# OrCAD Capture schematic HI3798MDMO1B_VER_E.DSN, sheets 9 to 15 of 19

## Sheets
9 SHEET09: size A
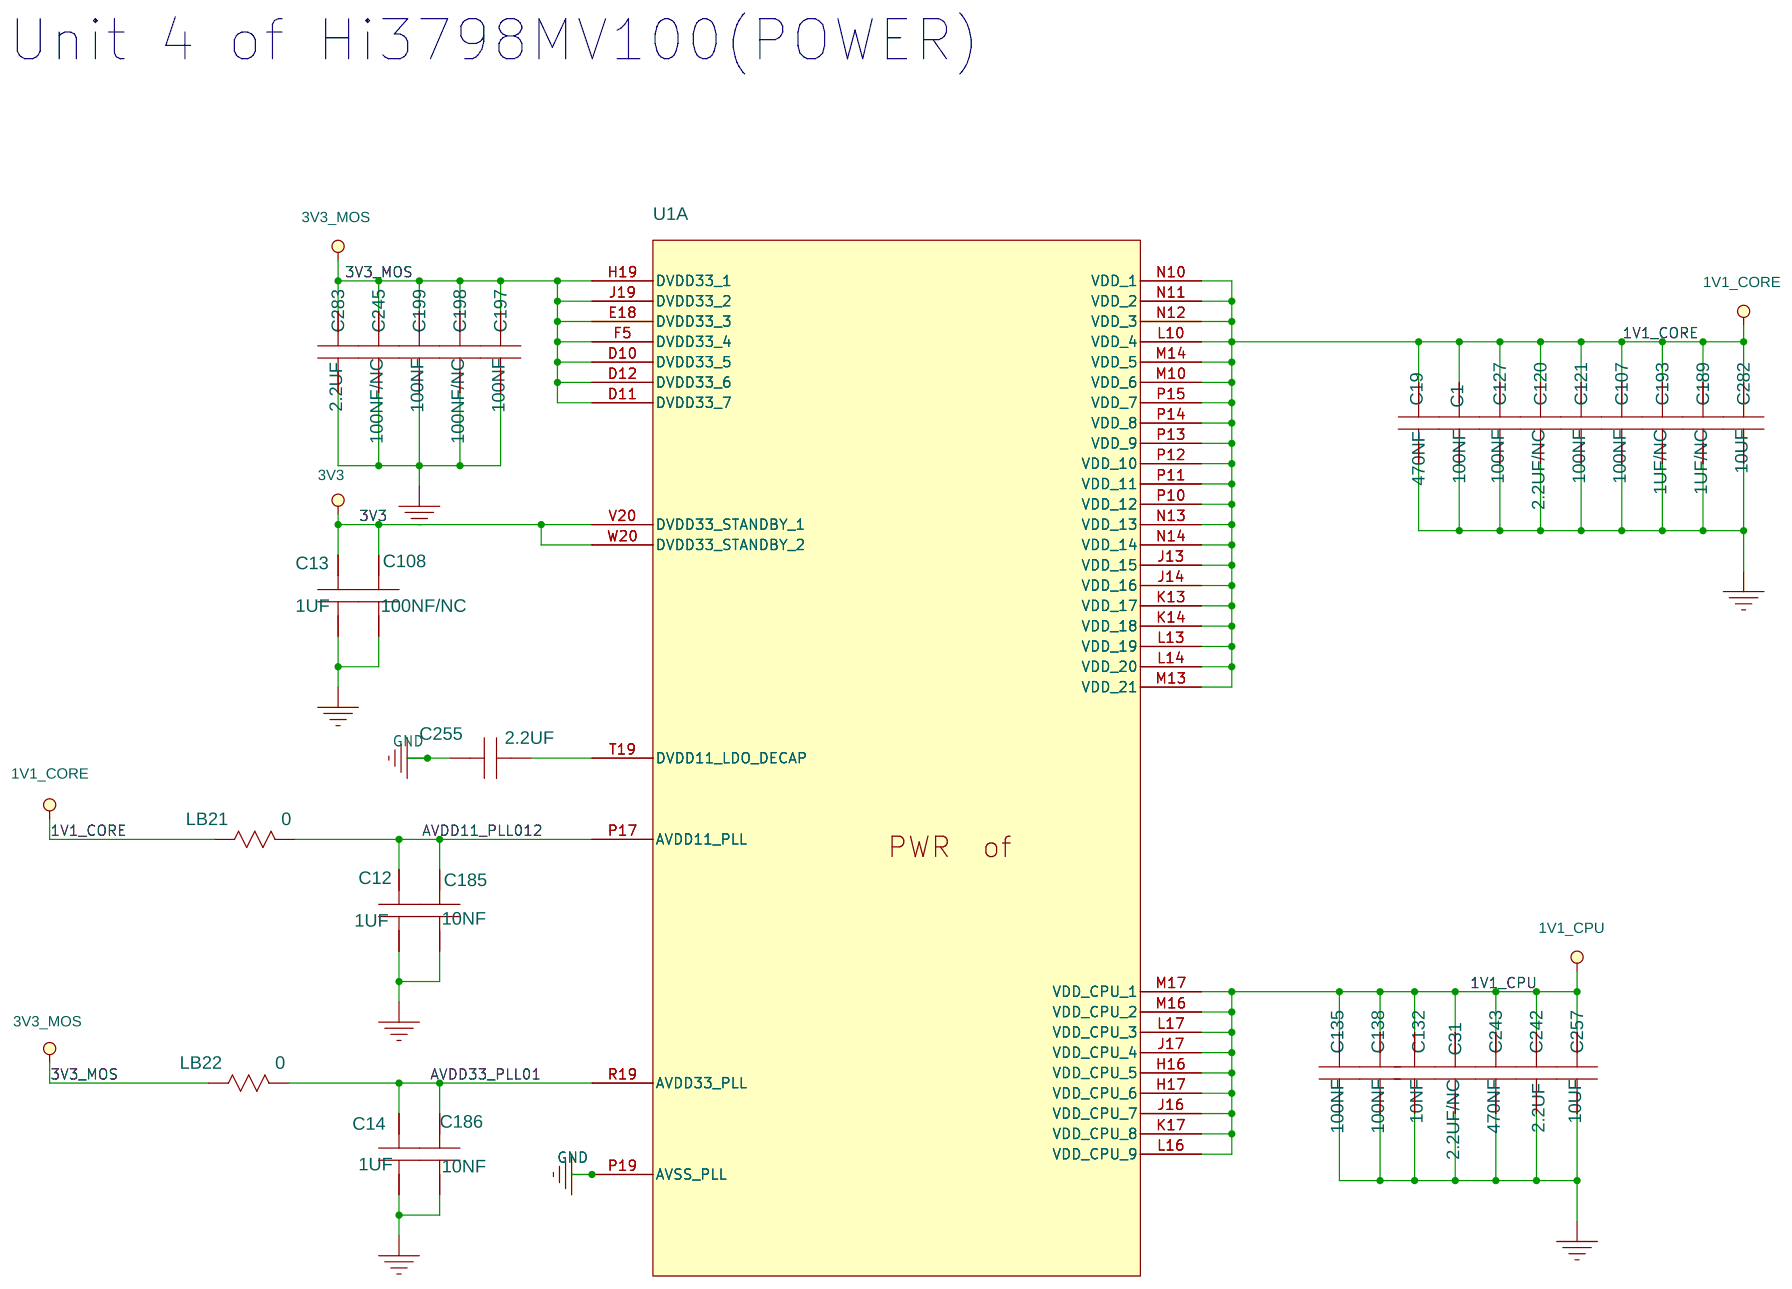
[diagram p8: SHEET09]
10 SHEET10: size A
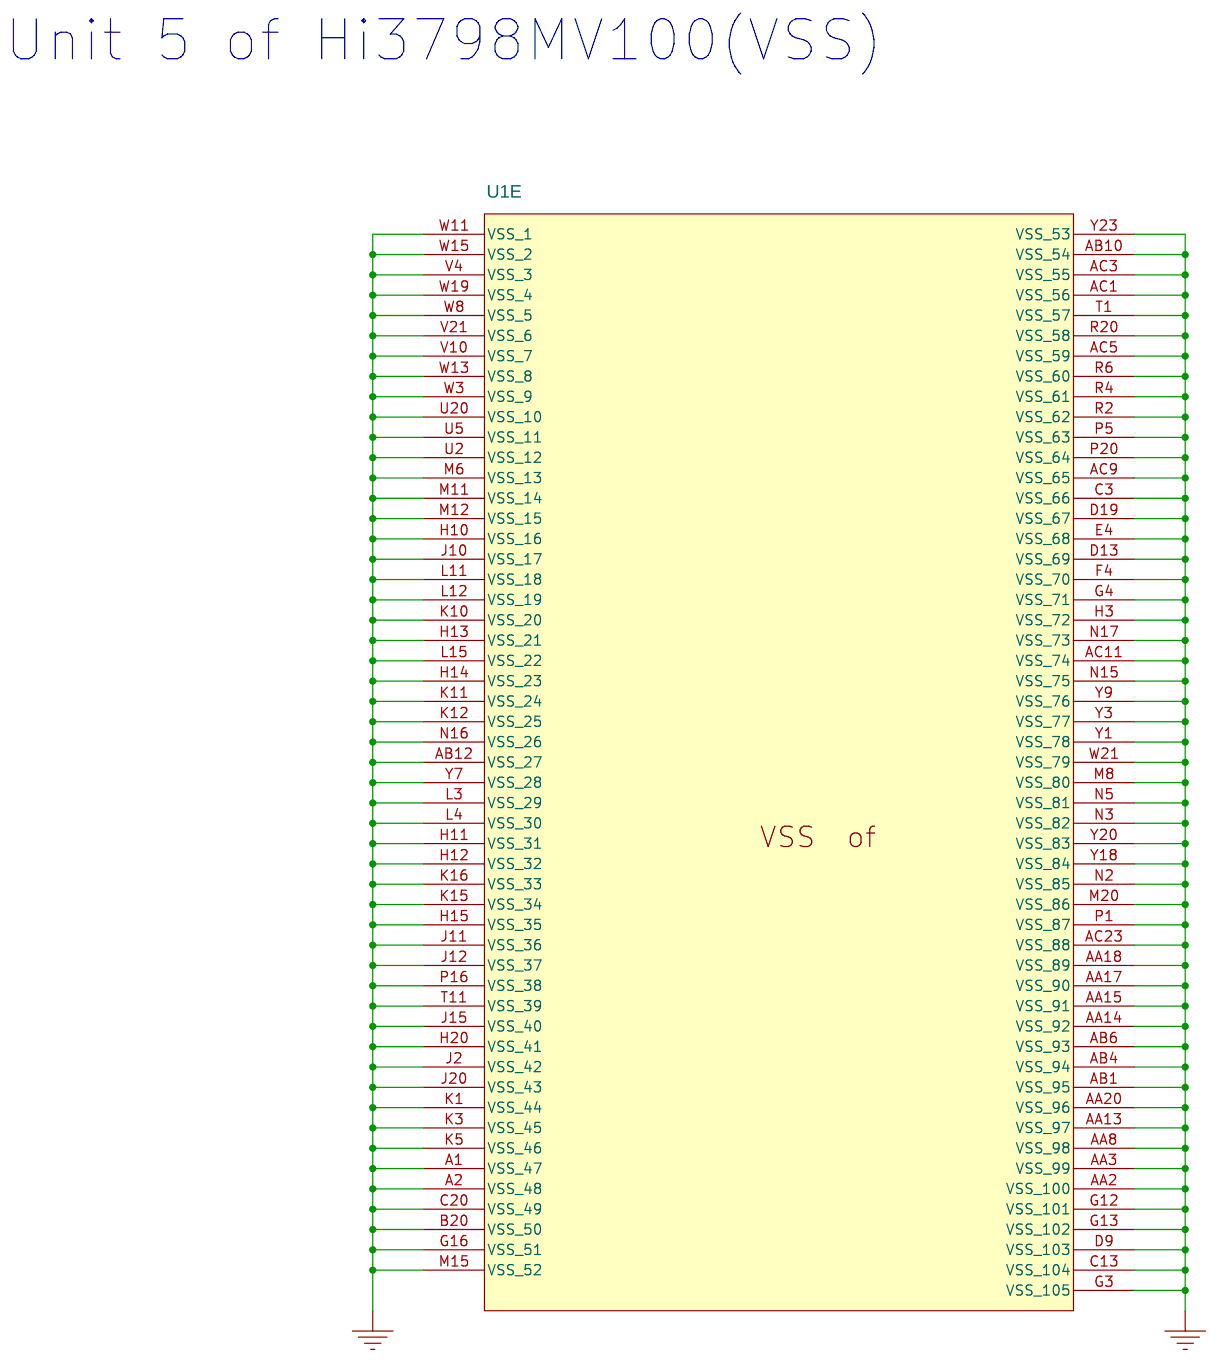
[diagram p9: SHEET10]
11 SHEET11: size Custom
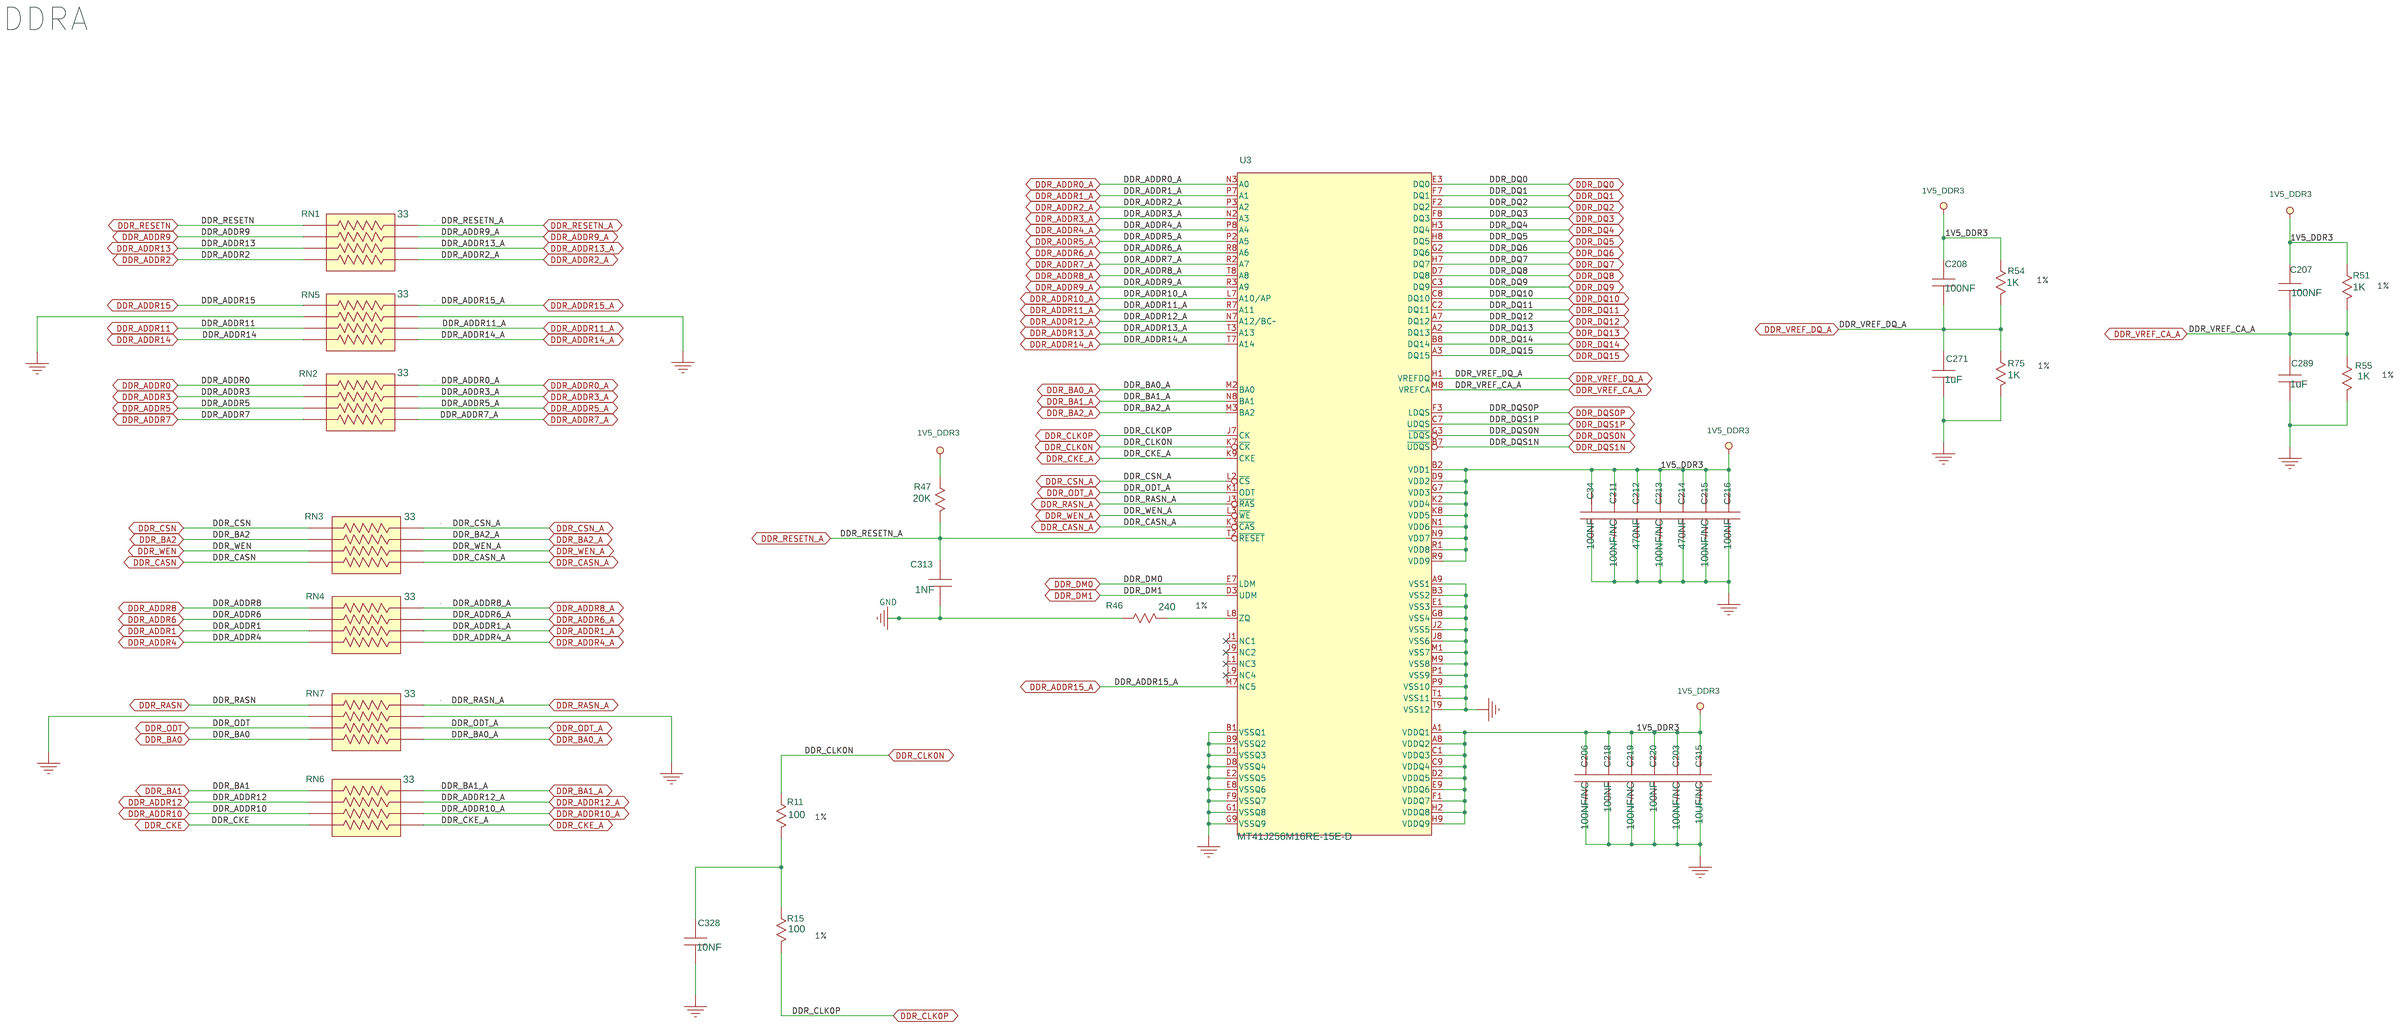
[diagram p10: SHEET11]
12 SHEET12: size Custom
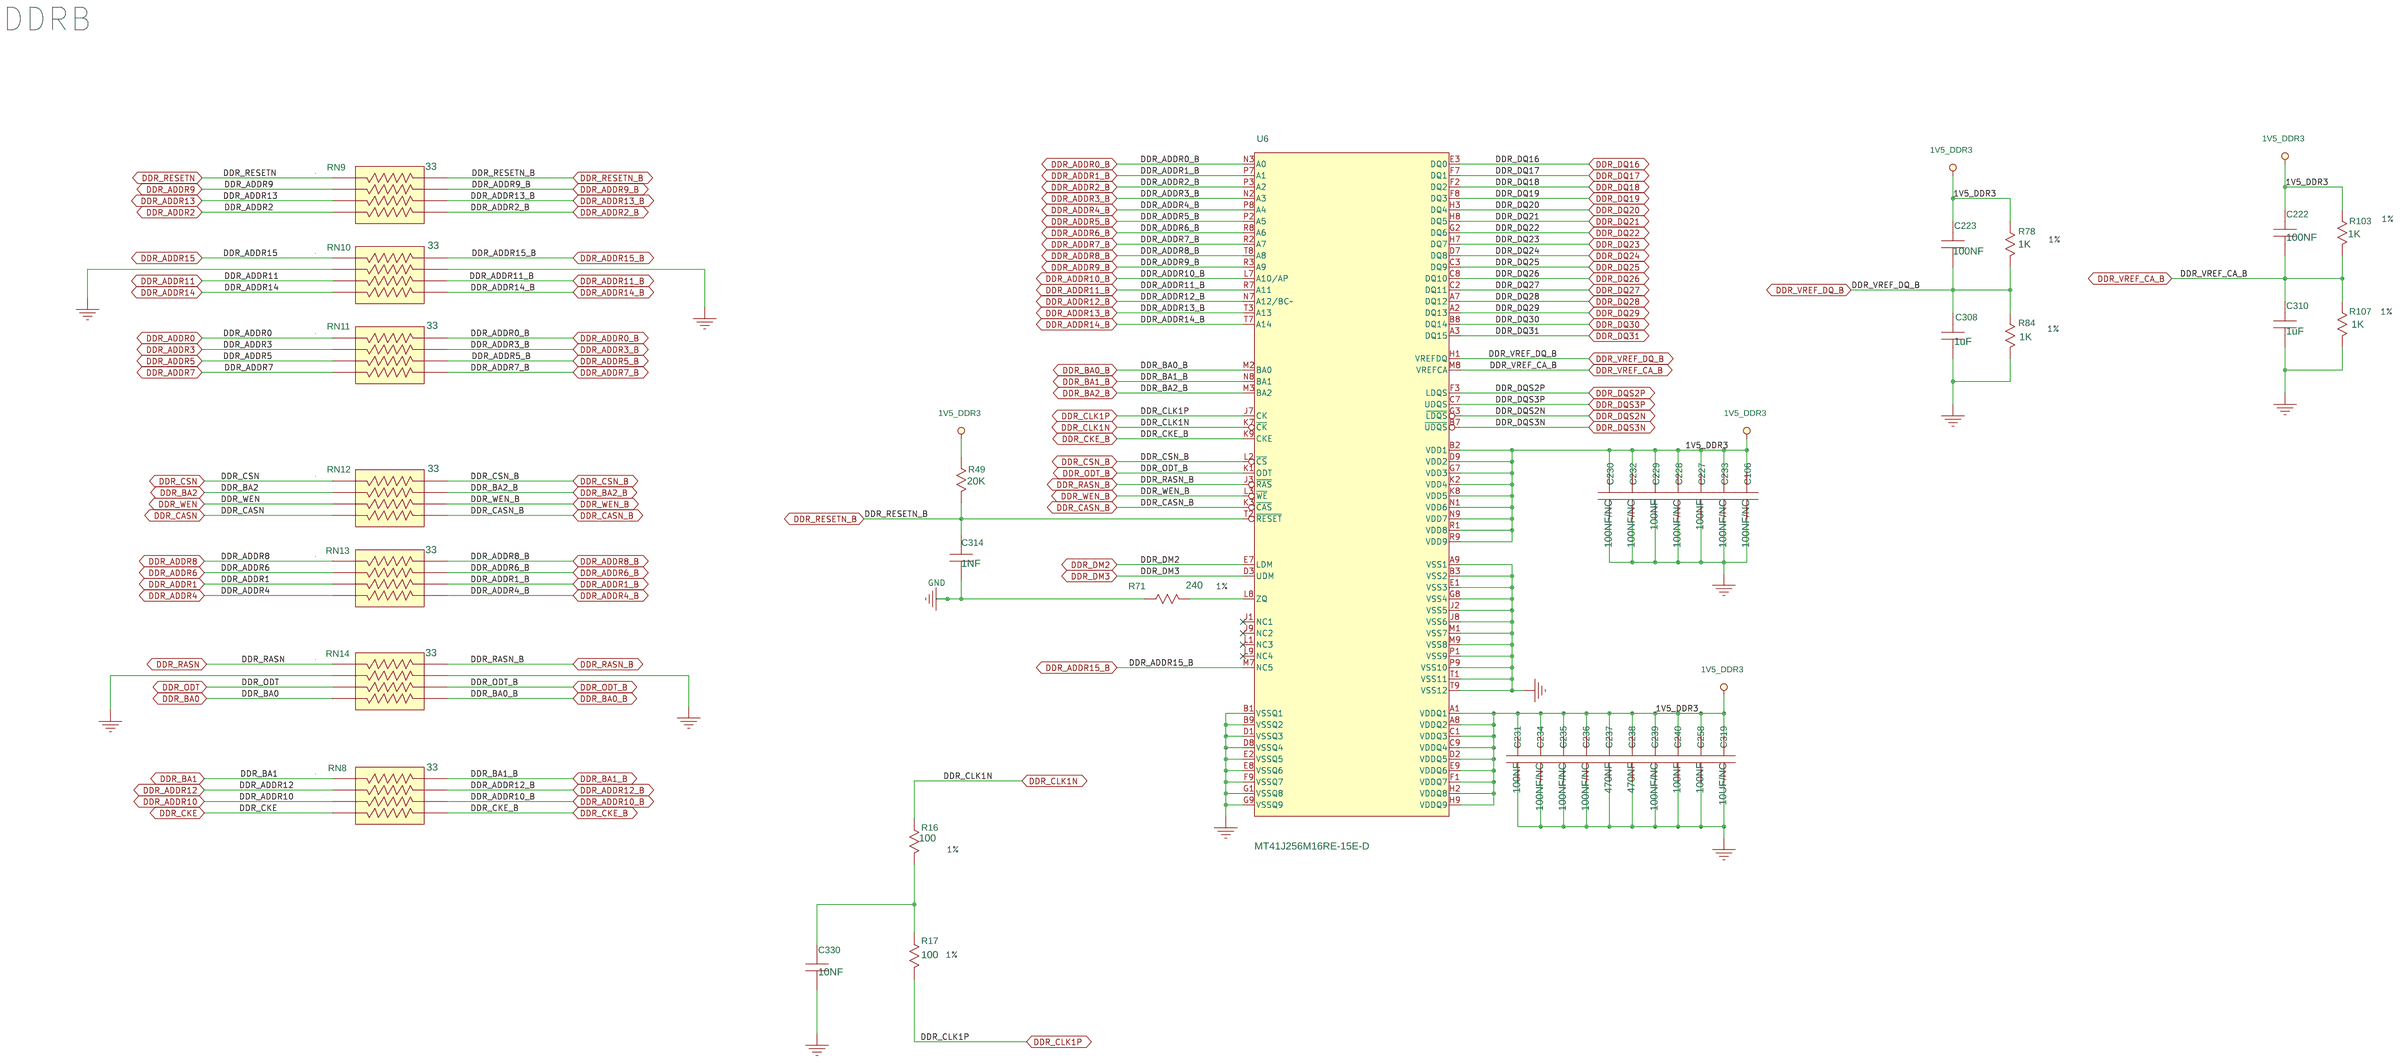
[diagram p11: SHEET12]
13 SHEET13: size Custom
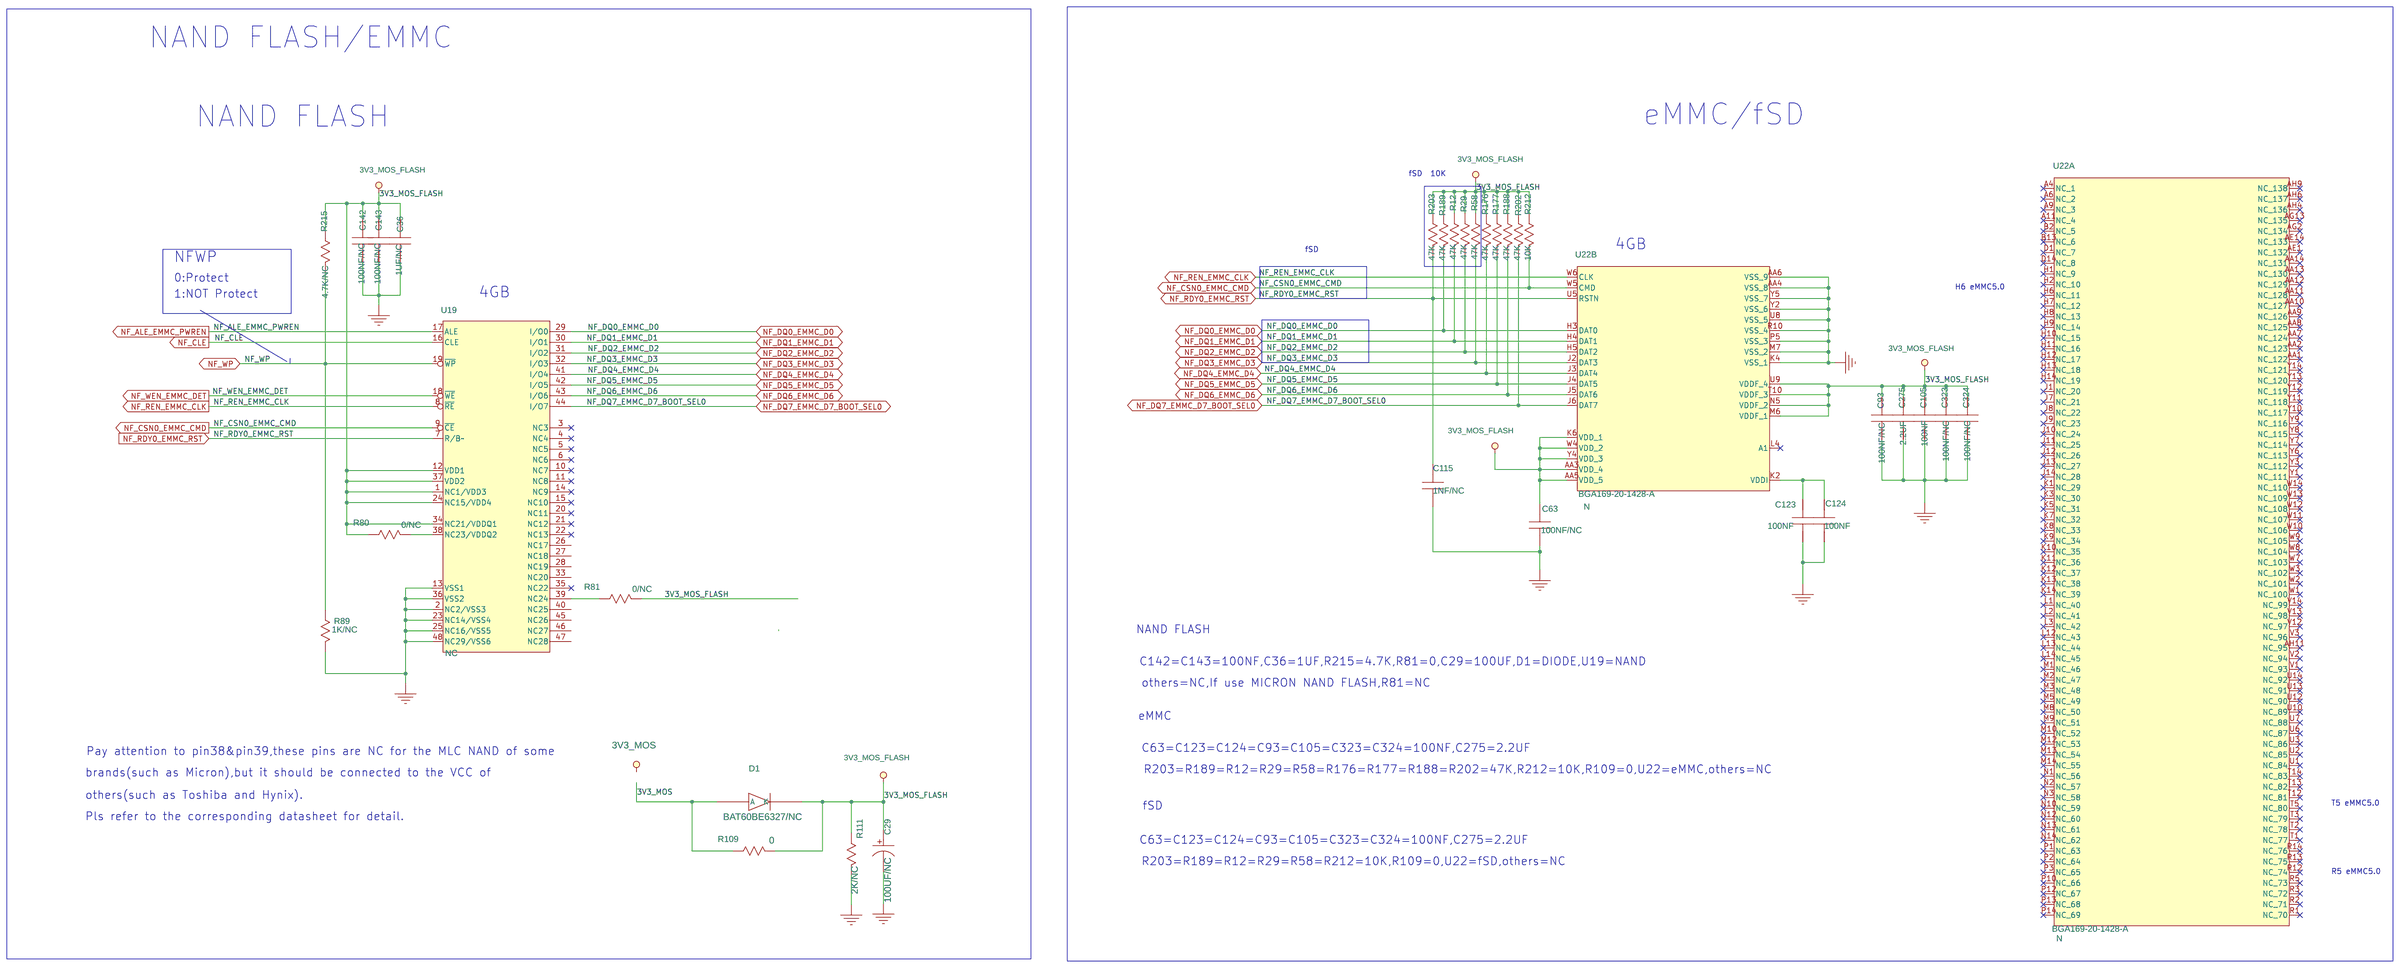
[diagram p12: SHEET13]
14 SHEET14: size Custom
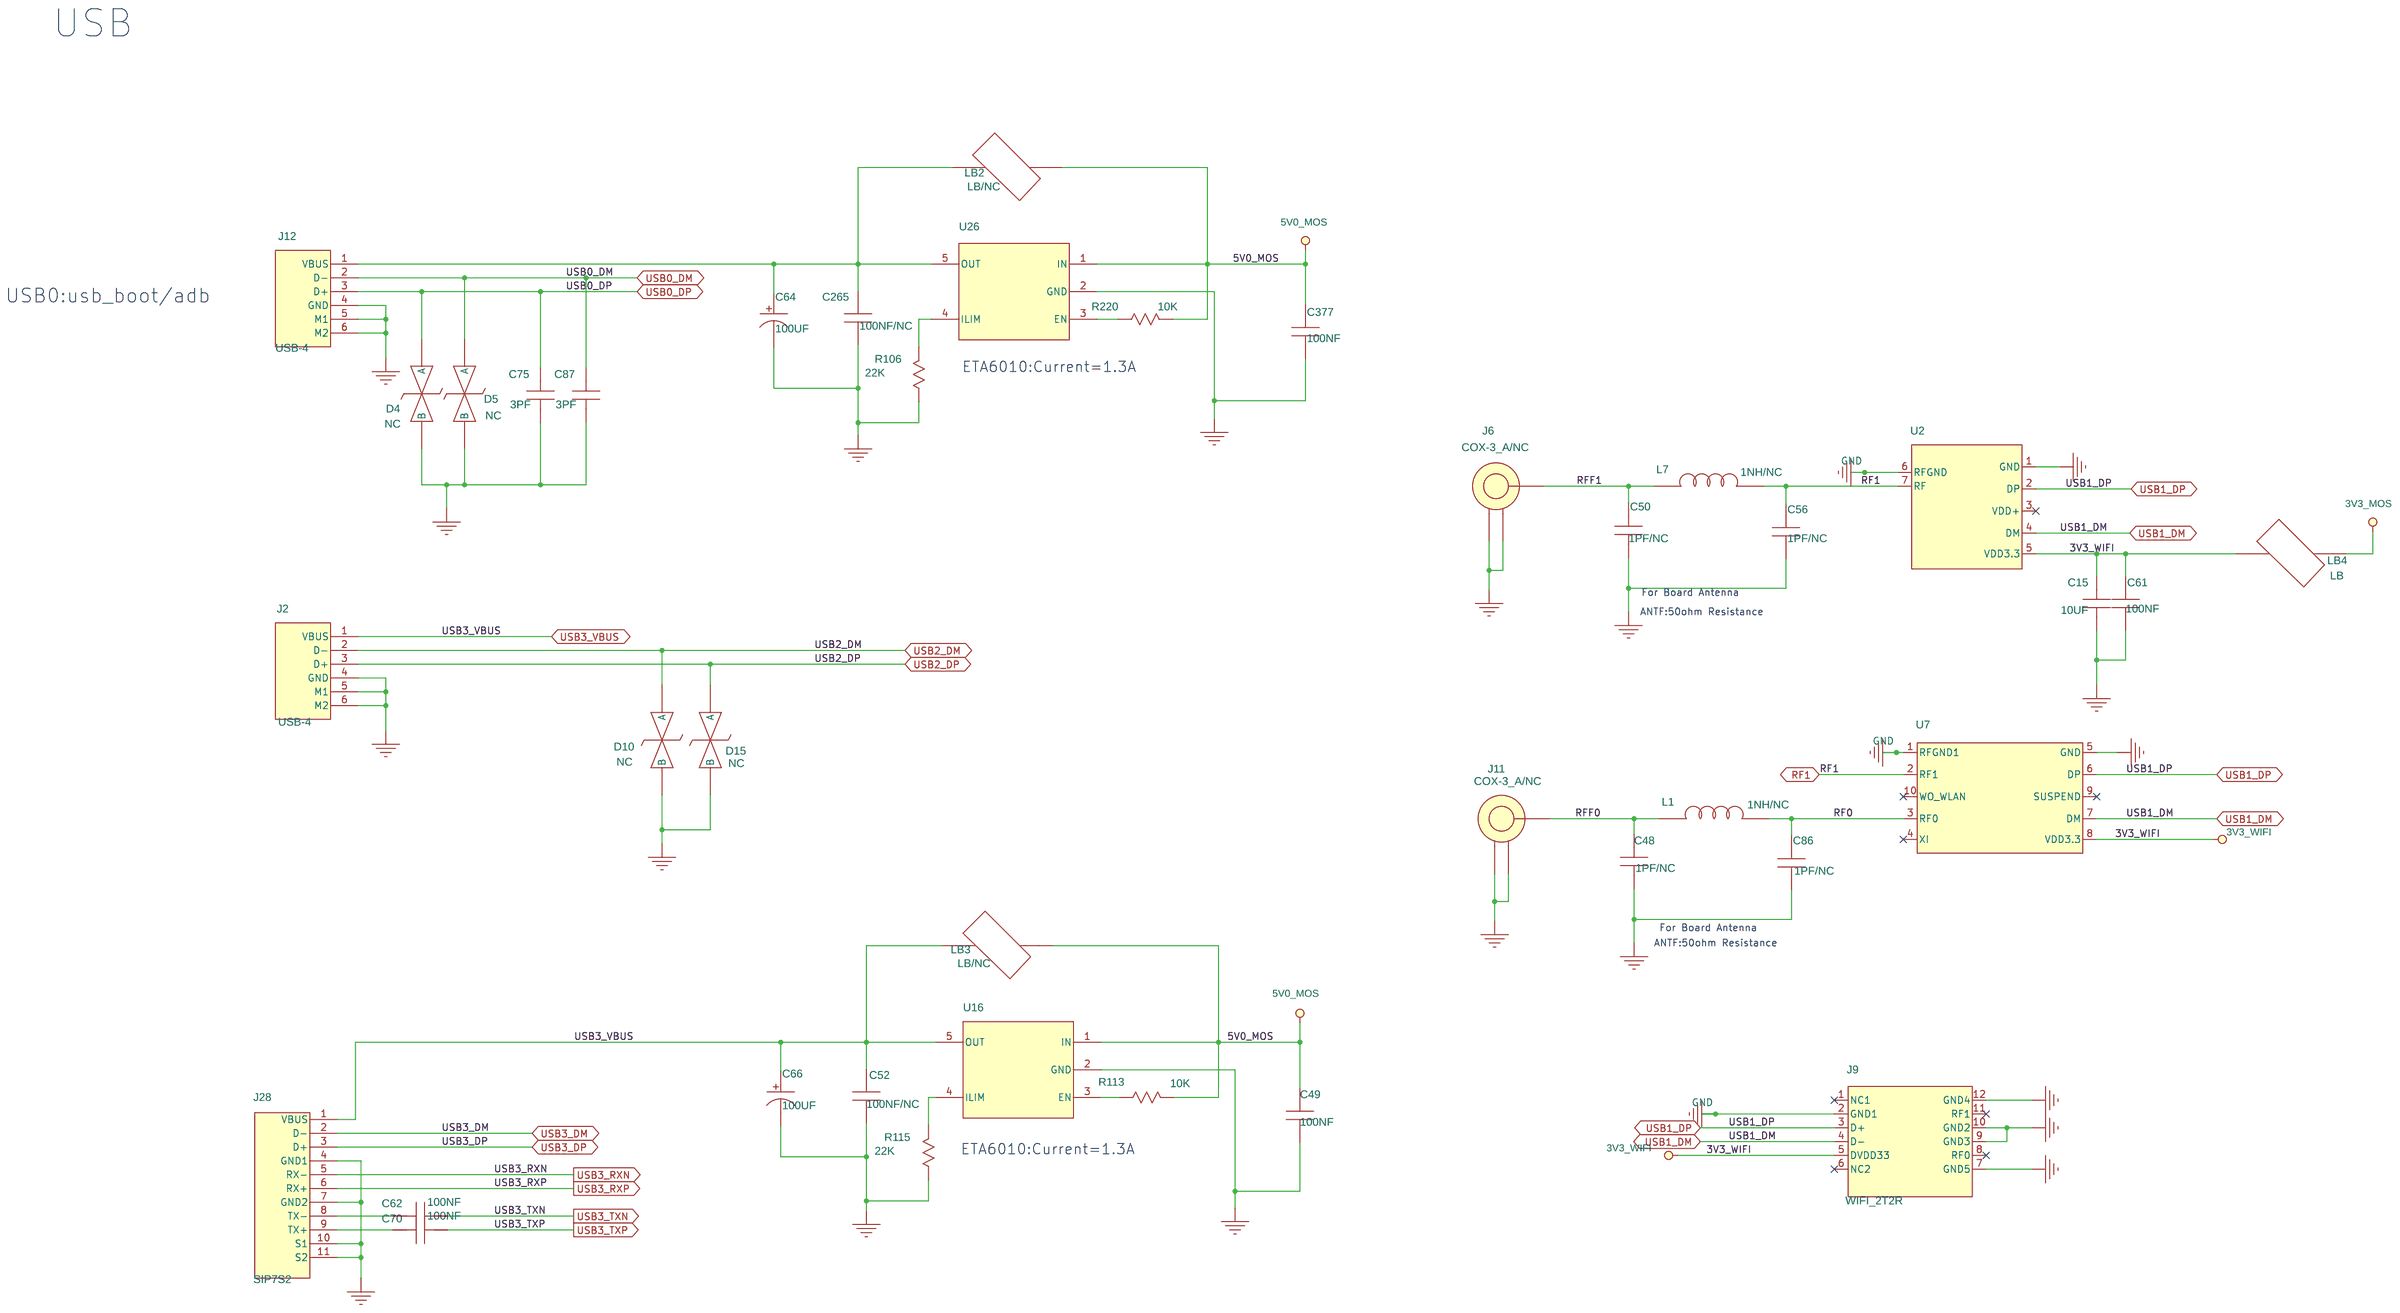
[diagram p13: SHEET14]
15 SHEET15: size Custom
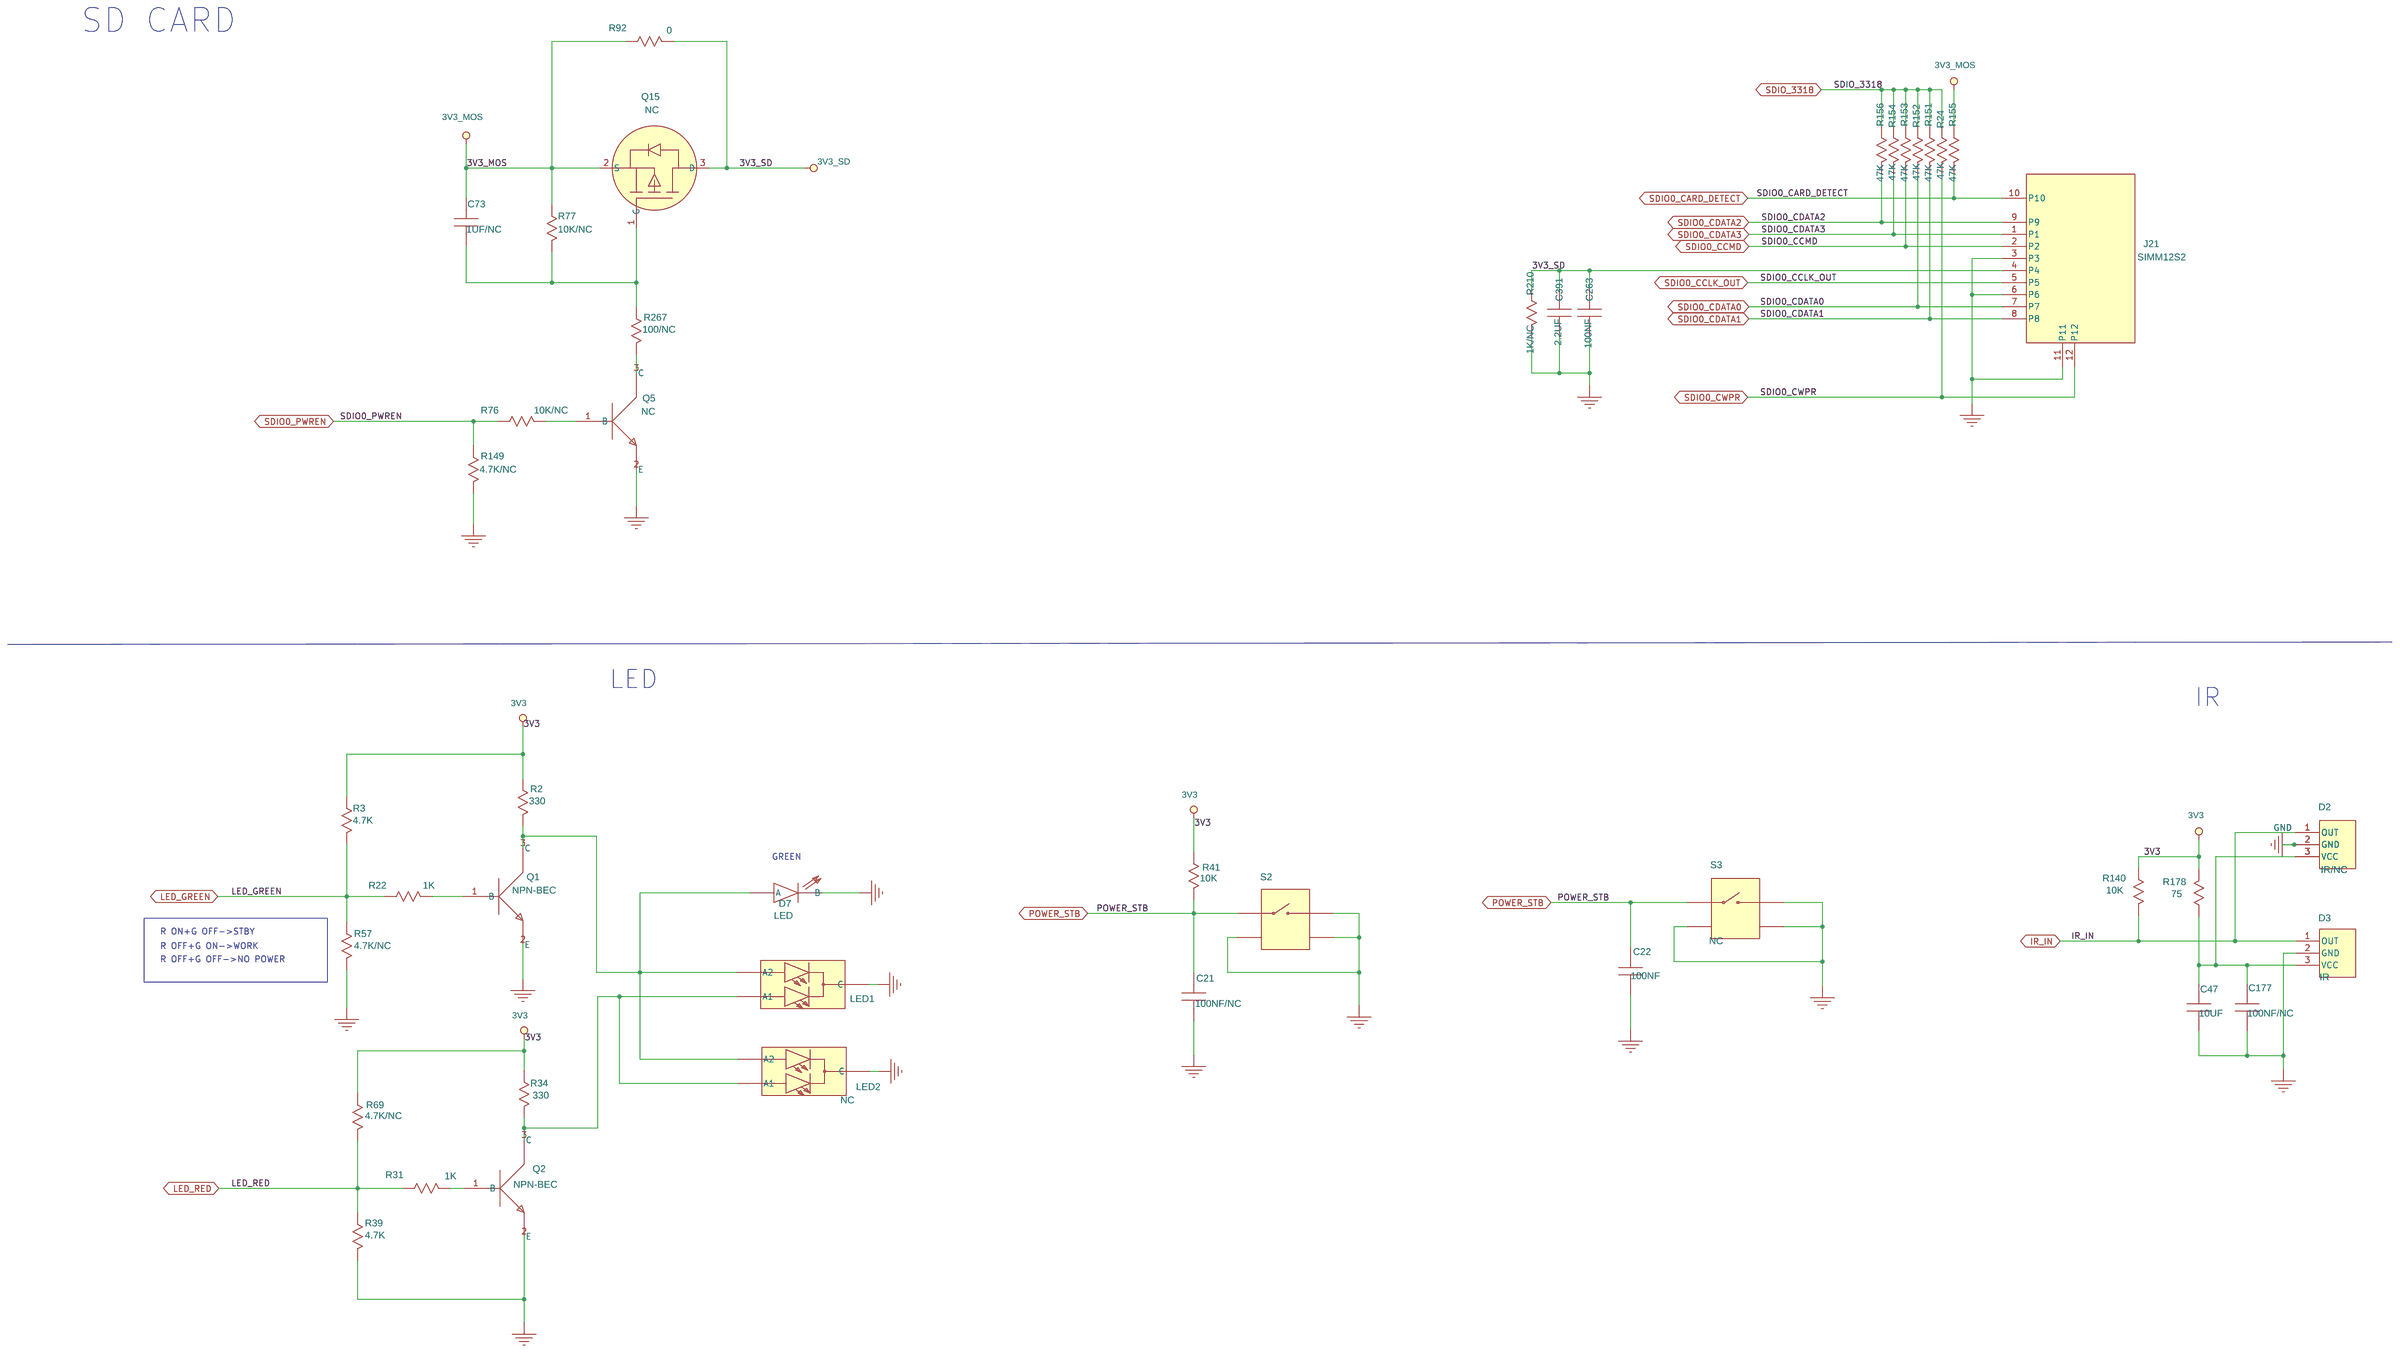
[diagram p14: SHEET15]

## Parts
sheet SHEET09
C1  100NF  [SC0402]
C12  1UF  [SC0402]
C13  1UF  [SC0603]
C14  1UF  [SC0402]
C19  470NF  [SC0402]
C31  2.2UF/NC  [HSC0402]
C107  100NF  [SC0402]
C108  100NF/NC  [SC0402]
C120  2.2UF/NC  [HSC0402]
C121  100NF  [SC0402]
C127  100NF  [SC0402]
C132  10NF  [SC0402]
C135  100NF  [SC0402]
C138  100NF  [SC0402]
C185  10NF  [SC0402]
C186  10NF  [SC0402]
C189  1UF/NC  [SC0402]
C193  1UF/NC  [SC0402]
C197  100NF  [SC0402]
C198  100NF/NC  [SC0402]
C199  100NF  [SC0402]
C242  2.2UF  [HSC0402]
C243  470NF  [SC0402]
C245  100NF/NC  [SC0402]
C255  2.2UF  [HSC0402]
C257  10UF  [SC0603]
C282  10UF  [SC0603]
C283  2.2UF  [SC0603]
LB21  0  [SL0603]
LB22  0  [SL0603]
U1  S40V300_19X19  [TFBGA395-32-2323]  (sections A,B,C,D,E)
sheet SHEET11
C34  100NF  [SC0402]
C203  100NF/NC  [SC0402]
C206  100NF/NC  [SC0402]
C207  100NF  [SC0402]
C208  100NF  [SC0402]
C211  100NF/NC  [SC0402]
C212  470NF  [SC0402]
C213  100NF/NC  [SC0402]
C214  470NF  [SC0402]
C215  100NF/NC  [SC0402]
C216  100NF  [SC0402]
C218  100NF  [SC0402]
C219  100NF/NC  [SC0402]
C220  100NF  [SC0402]
C271  1uF  [SC0402]
C289  1uF  [SC0402]
C313  1NF  [SC0402]
C315  10UF/NC  [SC0805]
C328  10NF  [SC0402]
R11  100  [SR0402]
R15  100  [SR0402]
R46  240  [SR0402]
R47  20K  [SR0402]
R51  1K  [SR0402]
R54  1K  [SR0402]
R55  1K  [SR0402]
R75  1K  [SR0402]
RN1  33  [SRN8-0804]
RN2  33  [SRN8-0804]
RN3  33  [SRN8-0804]
RN4  33  [SRN8-0804]
RN5  33  [SRN8-0804]
RN6  33  [SRN8-0804]
RN7  33  [SRN8-0804]
U3  MT41J256M16RE-15E-D  [BGA96-32-1609I]
sheet SHEET12
C106  100NF/NC  [SC0402]
C222  100NF  [SC0402]
C223  100NF  [SC0402]
C227  100NF  [SC0402]
C228  100NF/NC  [SC0402]
C229  100NF  [SC0402]
C230  100NF/NC  [SC0402]
C231  100NF  [SC0402]
C232  100NF/NC  [SC0402]
C233  100NF/NC  [SC0402]
C234  100NF/NC  [SC0402]
C235  100NF/NC  [SC0402]
C236  100NF/NC  [SC0402]
C237  470NF  [SC0402]
C238  470NF  [SC0402]
C239  100NF/NC  [SC0402]
C240  100NF  [SC0402]
C258  100NF  [SC0402]
C308  1uF  [SC0402]
C310  1uF  [SC0402]
C314  1NF  [SC0402]
C319  10UF/NC  [SC0805]
C330  10NF  [SC0402]
R16  100  [SR0402]
R17  100  [SR0402]
R49  20K  [SR0402]
R71  240  [SR0402]
R78  1K  [SR0402]
R84  1K  [SR0402]
R103  1K  [SR0402]
R107  1K  [SR0402]
RN8  33  [SRN8-0804]
RN9  33  [SRN8-0804]
RN10  33  [SRN8-0804]
RN11  33  [SRN8-0804]
RN12  33  [SRN8-0804]
RN13  33  [SRN8-0804]
RN14  33  [SRN8-0804]
U6  MT41J256M16RE-15E-D  [BGA96-32-1609I]
sheet SHEET13
C29  100UF/NC  [SAC6666]
C36  1UF/NC  [SC0603]
C63  100NF/NC  [SC0402]
C93  100NF/NC  [SC0402]
C105  100NF  [SC0402]
C115  1NF/NC  [SC0402]
C123  100NF  [SC0402]
C124  100NF  [SC0402]
C142  100NF/NC  [SC0402]
C143  100NF/NC  [SC0402]
C275  2.2UF  [SC0603]
C323  100NF/NC  [SC0402]
C324  100NF/NC  [SC0402]
D1  D_A  [HSOD323A]
R12  47K  [SR0402]
R29  47K  [SR0402]
R58  47K  [SR0402]
R80  0/NC  [SR0402]
R81  0/NC  [SR0402]
R89  1K/NC  [SR0402]
R109  0  [SR1206]
R111  2K/NC  [SR0603]
R176  47K  [SR0402]
R177  47K  [SR0402]
R188  47K  [SR0402]
R189  47K  [SR0402]
R202  47K  [SR0402]
R203  47K  [SR0402]
R212  10K  [SR0402]
R215  4.7K/NC  [SR0402]
U19  NC  [SOP48-20-720B]
U22  N  [BGA169-20-1428-A]  (sections A,B)
sheet SHEET14
C15  10UF  [SC0603]
C48  1PF/NC  [SC0402]
C49  100NF  [SC0603]
C50  1PF/NC  [SC0402]
C52  100NF/NC  [SC0603]
C56  1PF/NC  [SC0402]
C61  100NF  [SC0603]
C62  100NF  [SC0402]
C64  100UF  [SAC6666]
C66  100UF  [SAC6666]
C70  100NF  [SC0402]
C75  3PF  [SC0402]
C86  1PF/NC  [SC0402]
C87  3PF  [SC0402]
C265  100NF/NC  [SC0603]
C377  100NF  [SC0603]
D4  NC  [SC0402]
D5  NC  [SC0402]
D10  NC  [SC0402]
D15  NC  [SC0402]
J2  USB-4  [USB4-1415]
J6  COX-3_A/NC  [HSCOX-AMC-TM-A]
J9  WIFI_2T2R  [SIP12-2_0MM-1827]
J11  COX-3_A/NC  [HSCOX-AMC-TM-A]
J12  USB-4  [USB4-1415]
J28  SIP7S2  [USB3_0_9P_DIP_MAINSUPER]
L1  1NH/NC  [SL0402]
L7  1NH/NC  [SL0402]
LB2  LB/NC  [SL0603]
LB3  LB/NC  [SL0603]
LB4  LB  [SL0805]
R106  22K  [SR0402]
R113  10K  [SR0402]
R115  22K  [SR0402]
R220  10K  [SR0402]
U2  NC  [CDTWIFI]
U7  NC  [CDTWIFI10]
U16  NC  [SOT23-5]
U26  NC  [SOT23-5]
sheet SHEET15
C21  100NF/NC  [SC0603]
C22  100NF  [SC0603]
C47  10UF  [SC0603]
C73  1UF/NC  [SC0402]
C177  100NF/NC  [SC0402]
C263  100NF  [SC0603]
C391  2.2UF  [SC0603]
D2  IR/NC  [SEN3-100C]
D3  IR  [SEN3-100C]
D7  LED  [LED]
J21  SIMM12S2  [SOP12-SD-A]
LED1  LED2-3_E  [LED3C-100C]
LED2  NC  [LED3C-100C]
Q1  NPN-BEC  [SOT23]
Q2  NPN-BEC  [SOT23]
Q5  NC  [SOT23]
Q15  NC  [SOT23]
R2  330  [SR0402]
R3  4.7K  [SR0402]
R22  1K  [SR0402]
R24  47K  [SR0402]
R31  1K  [SR0402]
R34  330  [SR0402]
R39  4.7K  [SR0402]
R41  10K  [SR0402]
R57  4.7K/NC  [SR0402]
R69  4.7K/NC  [SR0402]
R76  10K/NC  [SR0603]
R77  10K/NC  [SR0603]
R92  0  [SR0603]
R140  10K  [SR0402]
R149  4.7K/NC  [SR0603]
R151  47K  [SR0402]
R152  47K  [SR0402]
R153  47K  [SR0402]
R154  47K  [SR0402]
R155  47K  [SR0402]
R156  47K  [SR0402]
R178  75  [SR0402]
R210  1K/NC  [SR0603]
R267  100/NC  [SR0603]
S2  NC  [TSW4-RG-C]
S3  NC  [TSW4-RG-C]

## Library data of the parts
C1 C34 C62 C63 C70 C93 C105-C108 C121 C123 C124 C127 C135 C138 C197-C199 C203 C206-C208 C211-C216 C218-C220 C222 C223 C227-C240 C245 C258 C271 C289 C308 C310 C323 C324 = C: %182%%238%%182%%168%%185%%164%%215%%247%%181%%231%%209%%185%(V): 10; %195%%232%%202%%246%: SMD陶瓷电容-10V-100NF-+/-10%-X5R-0402; %208%%161%%192%%224%%195%%251%%179%%198%: SMD陶瓷电容; CODE: 8070561; COMPONENT_HIGH_MAX: 0.55MM; DEVICE: C0402C104K8PAC_7867
C12 C14 C73 C189 C193 = C: %182%%238%%182%%168%%185%%164%%215%%247%%181%%231%%209%%185%(V): 10; %195%%232%%202%%246%: SMD陶瓷电容-10V-1000NF-+/-10%-X5R-0402-BT,TS16949; %208%%161%%192%%224%%195%%251%%179%%198%: SMD陶瓷电容; CODE: 8070612; COMPONENT_HIGH_MAX: 0.55MM; DEVICE: CV05X5R105K10AH
C13 C36 = C: %182%%238%%182%%168%%185%%164%%215%%247%%181%%231%%209%%185%(V): 25; %195%%232%%202%%246%: SMD陶瓷电容-25V-1000NF-+/-10%-X7R-0603; %208%%161%%192%%224%%195%%251%%179%%198%: SMD陶瓷电容; CODE: 8070962; COMPONENT_HIGH_MAX: 0.9MM; DEVICE: CETMK107B7105KA_T
C19 C243 = C: %182%%238%%182%%168%%185%%164%%215%%247%%181%%231%%209%%185%(V): 6.3; %195%%232%%202%%246%: SMD陶瓷电容-6.3V-470NF-+/-10%-X5R-0402; %208%%161%%192%%224%%195%%251%%179%%198%: SMD陶瓷电容; CODE: 8070625; COMPONENT_HIGH_MAX: 0.55MM; DEVICE: GRM155R60J474KE19D
C31 C120 C242 C255 = C: %182%%238%%182%%168%%185%%164%%215%%247%%181%%231%%209%%185%(V): 6.3; %195%%232%%202%%246%: SMD陶瓷电容-6.3V-2200NF-+/-20%-X5R-0402-TS16949; %208%%161%%192%%224%%195%%251%%179%%198%: SMD陶瓷电容; CODE: 8070667; COMPONENT_HIGH_MAX: 0.6MM; DEVICE: GRM155R60J225ME15D
C132 C185 C186 = C: %182%%238%%182%%168%%185%%164%%215%%247%%181%%231%%209%%185%(V): 16; %195%%232%%202%%246%: SMD陶瓷电容-16V-10NF-+/-10%-X7R-0402-BT,TS16949; %208%%161%%192%%224%%195%%251%%179%%198%: SMD陶瓷电容; CODE: 8070449; COMPONENT_HIGH_MAX: 0.55MM; DEVICE: GRM155R71C103KA01D
C15 C47 C257 C282 = C: %182%%238%%182%%168%%185%%164%%215%%247%%181%%231%%209%%185%(V): 6.3; %195%%232%%202%%246%: SMD陶瓷电容-6.3V-10000NF-+/-20%-X5R-0603-BT,TS16949; %208%%161%%192%%224%%195%%251%%179%%198%: SMD陶瓷电容; CODE: 8070649; COMPONENT_HIGH_MAX: 0.9MM; DEVICE: C1608X5R0J106MT0A0E
C283 = C: %182%%238%%182%%168%%185%%164%%215%%247%%181%%231%%209%%185%(V): 6.3; %195%%232%%202%%246%: SMD陶瓷电容-6.3V-2200NF-+/-10%-X5R-0603-BT; %208%%161%%192%%224%%195%%251%%179%%198%: SMD陶瓷电容; CODE: 8070563; COMPONENT_HIGH_MAX: 0.95MM; DEVICE: CM105X5R225K06AT
LB21 LB22 = R: %182%%238%%182%%168%%185%%166%%194%%202%(W): 0.06; %195%%232%%202%%246%: 片式厚膜电阻器-0.0625W-0OHM-< 50MOHM-0402-1A-BT; %208%%161%%192%%224%%195%%251%%179%%198%: 片式厚膜电阻器; %215%%232%%214%%181%%212%%202%%208%%237%%198%%171%%178%%238%: < 50MOHM; CODE: 7090800; DEVICE: RC0402JR_070R
U1 = Hi3798MV100: DEVICE: HI3798MV100_A
C115 C313 C314 = C: %182%%238%%182%%168%%185%%164%%215%%247%%181%%231%%209%%185%(V): 50; %195%%232%%202%%246%: SMD陶瓷电容-50V-1NF-+/-10%-X7R-0402-BT; %208%%161%%192%%224%%195%%251%%179%%198%: SMD陶瓷电容; CODE: 8070531; COMPONENT_HIGH_MAX: 0.56MM; DEVICE: 04025C102KAT2A
C315 C319 = C: %182%%238%%182%%168%%185%%164%%215%%247%%181%%231%%209%%185%(V): 6.3; %195%%232%%202%%246%: SMD陶瓷电容-6.3V-10000NF-+/-10%-X5R-0805-TS16949; %208%%161%%192%%224%%195%%251%%179%%198%: SMD陶瓷电容; CODE: 8070565; COMPONENT_HIGH_MAX: 1.45MM; DEVICE: CEJMK212BJ106KD_T
C328 C330 = C: %182%%238%%182%%168%%185%%164%%215%%247%%181%%231%%209%%185%(V): 16; %195%%232%%202%%246%: SMD陶瓷电容-16V-10NF-+/-10%-X7R-0402-BT,TS16949; %208%%161%%192%%224%%195%%251%%179%%198%: SMD陶瓷电容; CODE: 8070449; COMPONENT_HIGH_MAX: 0.56MM; DEVICE: GRM155R71C103KA01D
R11 R15-R17 = R: %195%%232%%202%%246%: 片式厚膜电阻器-0.0625W-100OHM-±5%-0402; CODE: 7090807; COMPONENT_HIGH_MAX: 0.4MM; DEVICE: RC0402JR_07100R
R46 R71 = R: %182%%238%%182%%168%%185%%166%%194%%202%(W): 0.06; %195%%232%%202%%246%: 片式厚膜电阻器-0.0625W-240OHM-+/- 1%-0402-BT; %208%%161%%192%%224%%195%%251%%179%%198%: 片式厚膜电阻器; %215%%232%%214%%181%%212%%202%%208%%237%%198%%171%%178%%238%: +/- 1%; CODE: 7091782; COMPONENT_HIGH_MAX: 0.4MM; DEVICE: RC0402FR_07240RL
R47 R49 = R: %182%%238%%182%%168%%185%%166%%194%%202%(W): 0.06; %195%%232%%202%%246%: 片式厚膜电阻器-0.0625W-20000OHM-+/-1%-0402-TS16949; %208%%161%%192%%224%%195%%251%%179%%198%: 片式厚膜电阻器; %215%%232%%214%%181%%212%%202%%208%%237%%198%%171%%178%%238%: +/-1%; CODE: 7091374; COMPONENT_HIGH_MAX: 0.65MM; DEVICE: RC_02W2002FT
R51 R54 R55 R75 R78 R84 R103 R107 = R: %182%%238%%182%%168%%185%%166%%194%%202%(W): 0.06; %195%%232%%202%%246%: 片式厚膜电阻器-0.0625W-1000OHM-+/-1%-0402-BT; %208%%161%%192%%224%%195%%251%%179%%198%: 片式厚膜电阻器; %215%%232%%214%%181%%212%%202%%208%%237%%198%%171%%178%%238%: +/-1%; CODE: 7091282; COMPONENT_HIGH_MAX: 0.4MM; DEVICE: RC0402FR_071KL
RN1-RN14 = RND8-4: %195%%232%%202%%246%: 电阻网络-0.0625W-33OHM-4个-8PIN-±5%-SMT-小型-独立式-2.0*1.0*0.45-0.5MM; %208%%161%%192%%224%%195%%251%%179%%198%: 电阻网络; %215%%232%%214%%181%%212%%202%%208%%237%%198%%171%%178%%238%: ±5%; CODE: 7080118; COMPONENT_HIGH_MAX: 0.55MM; DEVICE: YC124_JR_0733R
U3 U6 = MT41J256M16RE-15E-D_0: %195%%232%%202%%246%: DDR3 DRAM-4GBIT-800MHZ-16BIT-1.5V-FBGA96(无铅); %208%%161%%192%%224%%195%%251%%179%%198%: DDR3 DRAM; CODE: 40020173; COMPONENT_HIGH_MAX: -99999999MM; DEVICE: H5TQ4G63MFR_PBC_A
C29 = CP_4: %182%%238%%182%%168%%185%%164%%215%%247%%181%%231%%209%%185%(V): 16; %195%%232%%202%%246%: 非固体SMD铝电容-16V-100UF-+/-20%-6.3*5.4MM-极性-105DEGC-1000H-片式,温度敏感器件-工艺耐温250DEGC,5S; %208%%161%%192%%224%%195%%251%%179%%198%: 非固体SMD铝电容; CODE: 8010269; COMPONENT_HIGH_MAX: 5.7MM; DEVICE: UWT1C101MCL1GB
C142 C143 = C: %182%%238%%182%%168%%185%%164%%215%%247%%181%%231%%209%%185%(V): 16; %195%%232%%202%%246%: SMD陶瓷电容-16V-100NF-±10%-X7R-0402; %208%%161%%192%%224%%195%%251%%179%%198%: SMD陶瓷电容; CODE: 8070614; COMPONENT_HIGH_MAX: 0.6MM; DEVICE: RMEMK105BJ104KV_FR
C275 = C: %182%%238%%182%%168%%185%%164%%215%%247%%181%%231%%209%%185%(V): 6.3; %195%%232%%202%%246%: SMD陶瓷电容-6.3V-2200NF-+/-10%-X5R-0603; %208%%161%%192%%224%%195%%251%%179%%198%: SMD陶瓷电容; CODE: 8070563; COMPONENT_HIGH_MAX: 0.95MM; DEVICE: CM105X5R225K06AT
D1 = D_A_0: %195%%232%%202%%246%: 肖特基二极管-10V-3A-0.24V-SOD323-BT; %208%%161%%192%%224%%195%%251%%179%%198%: 肖特基二极管; CODE: 15010252; COMPONENT_HIGH_MAX: 1.1MM; DEVICE: BAT60BE6327/NC
R12 R24 R29 R58 R151-R156 R176 R177 R188 R189 R202 R203 = R: %182%%238%%182%%168%%185%%166%%194%%202%(W): 0.06; %195%%232%%202%%246%: 片式厚膜电阻器-0.0625W-47000OHM-+/-5%-0402-ELOM; %208%%161%%192%%224%%195%%251%%179%%198%: 片式厚膜电阻器; %215%%232%%214%%181%%212%%202%%208%%237%%198%%171%%178%%238%: +/-5%; CODE: 7090819; DEVICE: RC0402JR_0747K
R80 R81 = R: %182%%238%%182%%168%%185%%166%%194%%202%(W): 0.06; %195%%232%%202%%246%: 片式厚膜电阻器-0.0625W-0OHM-< 50MOHM-0402-1A-BT; %208%%161%%192%%224%%195%%251%%179%%198%: 片式厚膜电阻器; %215%%232%%214%%181%%212%%202%%208%%237%%198%%171%%178%%238%: < 50MOHM; CODE: 7090800; COMPONENT_HIGH_MAX: 0.4MM; DEVICE: RC0402JR_070R
R89 = R: %182%%238%%182%%168%%185%%166%%194%%202%(W): 0.06; %195%%232%%202%%246%: 片式厚膜电阻器-0.0625W-1000OHM-±5%-0402; %208%%161%%192%%224%%195%%251%%179%%198%: 片式厚膜电阻器; %215%%232%%214%%181%%212%%202%%208%%237%%198%%171%%178%%238%: ±5%; CODE: 7090809; COMPONENT_HIGH_MAX: 0.4MM; DEVICE: RC0402JR_071KL
R109 = R_6: %182%%238%%182%%168%%185%%166%%194%%202%(W): 0.25; %195%%232%%202%%246%: 片式厚膜电阻器-0.25W-0OHM-<50MOHM-1206-2A-BT; %208%%161%%192%%224%%195%%251%%179%%198%: 片式厚膜电阻器; %215%%232%%214%%181%%212%%202%%208%%237%%198%%171%%178%%238%: <50MOHM; CODE: 7090002; COMPONENT_HIGH_MAX: 0.7MM; DEVICE: RC1206JR_070RL
R111 = R_6: %182%%238%%182%%168%%185%%166%%194%%202%(W): 0.06; %195%%232%%202%%246%: 片式厚膜电阻器-0.0625W-1000OHM-±5%-0402; %208%%161%%192%%224%%195%%251%%179%%198%: 片式厚膜电阻器; %215%%232%%214%%181%%212%%202%%208%%237%%198%%171%%178%%238%: ±5%; CODE: 7090809; COMPONENT_HIGH_MAX: 0.4MM; DEVICE: RC0402JR_071KL
R113 R212 R220 = R: %182%%238%%182%%168%%185%%166%%194%%202%(W): 0.06; %195%%232%%202%%246%: 片式厚膜电阻器-0.0625W-10000OHM-+/-5%-0402-BT; %208%%161%%192%%224%%195%%251%%179%%198%: 片式厚膜电阻器; %215%%232%%214%%181%%212%%202%%208%%237%%198%%171%%178%%238%: +/-5%; CODE: 7090815; DEVICE: RC_02W103JT
R215 = R: %182%%238%%182%%168%%185%%166%%194%%202%(W): 0.06; %195%%232%%202%%246%: 片式厚膜电阻器-0.0625W-4700OHM-+/-5%-0402; %208%%161%%192%%224%%195%%251%%179%%198%: 片式厚膜电阻器; %215%%232%%214%%181%%212%%202%%208%%237%%198%%171%%178%%238%: +/-5%; CODE: 7090793; COMPONENT_HIGH_MAX: 0.4MM; DEVICE: RK73B1ELTP472J
U19 = MLC_NAND_0: CODE: *
U22 = N_0: CaptureCellPackProp: NA
C48 C50 C56 C86 = C: %182%%238%%182%%168%%185%%164%%215%%247%%181%%231%%209%%185%(V): 50; %195%%232%%202%%246%: SMD陶瓷电容-50V-0.001NF-+/-0.1PF-NPO-0402-BT; %208%%161%%192%%224%%195%%251%%179%%198%: SMD陶瓷电容; CODE: 8070578; COMPONENT_HIGH_MAX: 0.55MM; DEVICE: GRM1555C1H1R0B
C21 C22 C49 C52 C61 C75 C87 C263 C265 C377 = C: %182%%238%%182%%168%%185%%164%%215%%247%%181%%231%%209%%185%(V): 50; %195%%232%%202%%246%: SMD陶瓷电容-50V-100NF-±10%-X7R-0603; %208%%161%%192%%224%%195%%251%%179%%198%: SMD陶瓷电容; CODE: 8070627; COMPONENT_HIGH_MAX: 0.9MM; DEVICE: C1608X7R1H104KT000N
C64 C66 = CP: %182%%238%%182%%168%%185%%164%%215%%247%%181%%231%%209%%185%(V): 16; %195%%232%%202%%246%: 非固体SMD铝电容-16V-100UF-+/-20%-6.3*5.4MM-极性-105DEGC-1000H-片式,温度敏感器件-工艺耐温250DEGC,5S; %208%%161%%192%%224%%195%%251%%179%%198%: 非固体SMD铝电容; CODE: 8010269; COMPONENT_HIGH_MAX: 5.7MM; DEVICE: UWT1C101MCL1GB
D4 D5 D10 D15 = ULCE0505A015FR
J2 J12 = USB-4: %195%%232%%202%%246%: 网口连接器-单排-单端口-4PIN-4BIT-屏蔽-USB A型插座/侧面插入型-引脚长3.2MM-THT; %208%%161%%192%%224%%195%%251%%179%%198%: 网口连接器; CODE: 14080105; COMPONENT_HIGH_MAX: 7.12MM; DEVICE: 292303_1
J6 J11 = COX-3_A: %195%%232%%202%%246%: 射频连接器-同轴连接器-50OHM-直式-MALE-SMT-终端专用-终端专用; %208%%161%%192%%224%%195%%251%%179%%198%: 射频连接器; CODE: 14240060; COMPONENT_HIGH_MAX: 1.45MM; DEVICE: 51_3612_50_H
J9 = WIFI_0
J28 = SIP7S2
L1 L7 = L: %195%%232%%202%%246%: 贴片电感器-0.001UH-5％-0.045OHM-1.36A-15DEGC-0402; %208%%161%%192%%224%%195%%251%%179%%198%: 贴片电感器; CODE: 10031232; COMPONENT_HIGH_MAX: 0.66MM; DEVICE: 0402CS_1N0XJLW
LB2 LB3 = LB_v2: %195%%232%%202%%246%: EMI磁珠-30OHM-0.05OHM-0.4A-0603-; %208%%161%%192%%224%%195%%251%%179%%198%: EMI磁珠; CODE: 10070003; COMPONENT_HIGH_MAX: 0.95MM; DEVICE: MGLB1608_030T_LF
LB4 = LB_v2: %195%%232%%202%%246%: EMI磁珠-+/-25%-220OHM-0.05OHM-2A-0805; %208%%161%%192%%224%%195%%251%%179%%198%: EMI磁珠; CODE: 10070012; COMPONENT_HIGH_MAX: 1.05MM; DEVICE: MGLB2012_220T_LF
R106 R115 = R: %182%%238%%182%%168%%185%%166%%194%%202%(W): 0.06; %195%%232%%202%%246%: 片式厚膜电阻器-0.0625W-22000OHM-+/-1%-0402; %208%%161%%192%%224%%195%%251%%179%%198%: 片式厚膜电阻器; %215%%232%%214%%181%%212%%202%%208%%237%%198%%171%%178%%238%: +/-1%; CODE: 7090798; COMPONENT_HIGH_MAX: 0.4MM; DEVICE: RK73H1ELTP2202F
U2 = CDT-CELKF04_0
U7 = CDT-CELKF10_0
U16 U26 = ETA6010: DEVICE: ETA6010_SGM2551A
C177 = C: %182%%238%%182%%168%%185%%164%%215%%247%%181%%231%%209%%185%(V): 16; %195%%232%%202%%246%: SMD陶瓷电容-16V-100NF-+/-10%-X7R-0402-BT; %208%%161%%192%%224%%195%%251%%179%%198%: SMD陶瓷电容; CODE: 8070614; COMPONENT_HIGH_MAX: 0.6MM; DEVICE: RMEMK105BJ104KV_FR
C391 = C: %182%%238%%182%%168%%185%%164%%215%%247%%181%%231%%209%%185%(V): 10; %195%%232%%202%%246%: SMD陶瓷电容-10V-2200NF-+/-10%-X5R-0603; %208%%161%%192%%224%%195%%251%%179%%198%: SMD陶瓷电容; CODE: 8070573; COMPONENT_HIGH_MAX: 0.9MM; DEVICE: GRM188R61A225KE34D
D2 D3 = IRM-3638A_0: %195%%232%%202%%246%: 红外遥控接收头-5V-0.001A-0.015KM-38KHZ-940NM-7*8*3.75; %208%%161%%192%%224%%195%%251%%179%%198%: 红外遥控接收头; COMPONENT_HIGH_MAX: 6.95MM; DEVICE: TSOP4838
D7 = DLED1: %195%%232%%202%%246%: 发光二极管-0.006CD-绿色/565NM-30MA-D3-PCB预热的TOP面温度<100DEGC,引脚温度>100DEGC时间小于60S,过锡时间3~8S推荐<5S; %208%%161%%192%%224%%195%%251%%179%%198%: 发光二极管; CODE: 15020005; COMPONENT_HIGH_MAX: 5.5MM; DEVICE: 204GD_E_A
J21 = SIMM12S2_0
LED1 LED2 = LED2-3_E: %195%%232%%202%%246%: 发光二极管-0.25CD-红绿625NM/570NM-25MA-插装-共阴-终端专用-00500098; CODE: 15020190; COMPONENT_HIGH_MAX: 7.2MM; DEVICE: 209_3SYGSURC_S530_A3HW
Q1 Q2 Q5 = NPN-BEC: %195%%232%%202%%246%: 三极管-NPN-45V-100MA-225MW-200MV@100MA-SOT-23-180@2MA; %208%%161%%192%%224%%195%%251%%179%%198%: 三极管; CODE: 15050206; COMPONENT_HIGH_MAX: 1.26MM; DEVICE: BC847AE6327
Q15 = FETP-GSD: %195%%232%%202%%246%: MOSFET-P沟道--8V--3A-50MOHM--8V-SOT23; %208%%161%%192%%224%%195%%251%%179%%198%: MOSFET; CODE: 15060134; COMPONENT_HIGH_MAX: 1.11MM; DEVICE: IRLML6401TR
R2 R22 R31 R34 = R: %182%%238%%182%%168%%185%%166%%194%%202%(W): 0.06; %195%%232%%202%%246%: 片式厚膜电阻器-0.0625W-1000OHM-+/-5%-0402-BT; %208%%161%%192%%224%%195%%251%%179%%198%: 片式厚膜电阻器; %215%%232%%214%%181%%212%%202%%208%%237%%198%%171%%178%%238%: +/-5%; CODE: 7090809; COMPONENT_HIGH_MAX: 0.4MM; DEVICE: RC0402JR_071KL
R3 R39 R57 R69 = R: %182%%238%%182%%168%%185%%166%%194%%202%(W): 0.06; %195%%232%%202%%246%: 片式厚膜电阻器-0.0625W-4700OHM-+/-5%-0402-BT; %208%%161%%192%%224%%195%%251%%179%%198%: 片式厚膜电阻器; %215%%232%%214%%181%%212%%202%%208%%237%%198%%171%%178%%238%: +/-5%; CODE: 7090793; COMPONENT_HIGH_MAX: 0.4MM; DEVICE: RK73B1ELTP472J
R41 R140 = R: %182%%238%%182%%168%%185%%166%%194%%202%(W): 0.06; %195%%232%%202%%246%: 片式厚膜电阻器-0.0625W-10000OHM-+/-5%-0402-BT; %208%%161%%192%%224%%195%%251%%179%%198%: 片式厚膜电阻器; %215%%232%%214%%181%%212%%202%%208%%237%%198%%171%%178%%238%: +/-5%; CODE: 7090815; COMPONENT_HIGH_MAX: 0.4MM; DEVICE: RC_02W103JT
R76 R77 = R: %182%%238%%182%%168%%185%%166%%194%%202%(W): 0.1; %195%%232%%202%%246%: 片式厚膜电阻器-0.1W-10000OHM-+/-1%-0603; %208%%161%%192%%224%%195%%251%%179%%198%: 片式厚膜电阻器; %215%%232%%214%%181%%212%%202%%208%%237%%198%%171%%178%%238%: +/-1%; CODE: 7090889; COMPONENT_HIGH_MAX: 0.55MM; DEVICE: RC_03K1002FT
R92 = R: %182%%238%%182%%168%%185%%166%%194%%202%(W): 0.1; %195%%232%%202%%246%: 片式厚膜电阻器-0.1W-0OHM-<50MOHM-0603-1A-BT,TS16949; %208%%161%%192%%224%%195%%251%%179%%198%: 片式厚膜电阻器; %215%%232%%214%%181%%212%%202%%208%%237%%198%%171%%178%%238%: <50MOHM; CODE: 7090522; COMPONENT_HIGH_MAX: 0.55MM; DEVICE: RC0603JR_070RL
R149 = R: %182%%238%%182%%168%%185%%166%%194%%202%(W): 0.1; %195%%232%%202%%246%: 片式厚膜电阻器-0.1W-4700OHM-+/-5%-0603-抗硫化; %208%%161%%192%%224%%195%%251%%179%%198%: 片式厚膜电阻器; %215%%232%%214%%181%%212%%202%%208%%237%%198%%171%%178%%238%: +/-5%; CODE: 7090246; DEVICE: RC0603JR_074K7
R178 = R: %182%%238%%182%%168%%185%%166%%194%%202%(W): 0.06; %195%%232%%202%%246%: 片式厚膜电阻器-0.0625W-75OHM-+/-1%-0402; %208%%161%%192%%224%%195%%251%%179%%198%: 片式厚膜电阻器; %215%%232%%214%%181%%212%%202%%208%%237%%198%%171%%178%%238%: +/-1%; CODE: 7091321; COMPONENT_HIGH_MAX: 0.4MM; DEVICE: RC_02W750FT
R210 = R: %182%%238%%182%%168%%185%%166%%194%%202%(W): 0.1; %195%%232%%202%%246%: 片式厚膜电阻器-0.1W-1000OHM-+/-5%-0603; %208%%161%%192%%224%%195%%251%%179%%198%: 片式厚膜电阻器; %215%%232%%214%%181%%212%%202%%208%%237%%198%%171%%178%%238%: +/-5%; CODE: 7090277; COMPONENT_HIGH_MAX: 0.55MM; DEVICE: RC0603JR_071K
R267 = R: %182%%238%%182%%168%%185%%166%%194%%202%(W): 0.06; %195%%232%%202%%246%: 片式厚膜电阻器-0.1W-100OHM-±5%-0603; %208%%161%%192%%224%%195%%251%%179%%198%: 片式厚膜电阻器; %215%%232%%214%%181%%212%%202%%208%%237%%198%%171%%178%%238%: ±5%; CODE: 7090269; COMPONENT_HIGH_MAX: 0.55MM; DEVICE: RC0603JR_07100RL
S2 S3 = PSW4_A: CODE: 16100051

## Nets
1V1_CORE: C1.1(A) C19.1(A) C107.1(A) C120.1(A) C121.1(A) C127.1(A) C189.1(A) C193.1(A) C282.1(A) LB21.1(A) U1.J13(VDD_15) U1.J14(VDD_16) U1.K13(VDD_17) U1.K14(VDD_18) U1.L10(VDD_4) U1.L13(VDD_19) U1.L14(VDD_20) U1.M10(VDD_6) U1.M13(VDD_21) U1.M14(VDD_5) U1.N10(VDD_1) U1.N11(VDD_2) U1.N12(VDD_3) U1.N13(VDD_13) U1.N14(VDD_14) U1.P10(VDD_12) U1.P11(VDD_11) U1.P12(VDD_10) U1.P13(VDD_9) U1.P14(VDD_8) U1.P15(VDD_7) ; also on sheet 4 6 7
1V1_CPU: C31.1(A) C132.1(A) C135.1(A) C138.1(A) C242.1(A) C243.1(A) C257.1(A) U1.H16(VDD_CPU_5) U1.H17(VDD_CPU_6) U1.J16(VDD_CPU_7) U1.J17(VDD_CPU_4) U1.K17(VDD_CPU_8) U1.L16(VDD_CPU_9) U1.L17(VDD_CPU_3) U1.M16(VDD_CPU_2) U1.M17(VDD_CPU_1) ; also on sheet 4
1V5_DDR3: C34.1(A) C106.1(A) C203.1(A) C206.1(A) C207.1(A) C208.1(A) C211.1(A) C212.1(A) C213.1(A) C214.1(A) C215.1(A) C216.1(A) C218.1(A) C219.1(A) C220.1(A) C222.1(A) C223.1(A) C227.1(A) C228.1(A) C229.1(A) C230.1(A) C231.1(A) C232.1(A) C233.1(A) C234.1(A) C235.1(A) C236.1(A) C237.1(A) C238.1(A) C239.1(A) C240.1(A) C258.1(A) C315.1(A) C319.1(A) R47.1(A) R49.1(A) R51.1(A) R54.1(A) R78.1(A) R103.1(A) U3.A1(VDDQ1) U3.A8(VDDQ2) U3.B2(VDD1) U3.C1(VDDQ3) U3.C9(VDDQ4) U3.D2(VDDQ5) U3.D9(VDD2) U3.E9(VDDQ6) U3.F1(VDDQ7) U3.G7(VDD3) U3.H2(VDDQ8) U3.H9(VDDQ9) U3.K2(VDD4) U3.K8(VDD5) U3.N1(VDD6) U3.N9(VDD7) U3.R1(VDD8) U3.R9(VDD9) U6.A1(VDDQ1) U6.A8(VDDQ2) U6.B2(VDD1) U6.C1(VDDQ3) U6.C9(VDDQ4) U6.D2(VDDQ5) U6.D9(VDD2) U6.E9(VDDQ6) U6.F1(VDDQ7) U6.G7(VDD3) U6.H2(VDDQ8) U6.H9(VDDQ9) U6.K2(VDD4) U6.K8(VDD5) U6.N1(VDD6) U6.N9(VDD7) U6.R1(VDD8) U6.R9(VDD9) ; also on sheet 4 8
3V3: C13.1(A) C108.1(A) R2.1(A) R3.1(A) R34.1(A) R41.1(A) R69.1(A) R140.2(B) R178.2(B) U1.V20(DVDD33_STANDBY_1) U1.W20(DVDD33_STANDBY_2) ; also on sheet 4 5 6 17
3V3_MOS: C73.1(A) C197.1(A) C198.1(A) C199.1(A) C245.1(A) C283.1(A) D1.2(A) LB4.2 LB22.1(A) Q15.2(S) R77.1(A) R92.1(A) R109.1(A) R155.1(A) U1.D10(DVDD33_5) U1.D11(DVDD33_7) U1.D12(DVDD33_6) U1.E18(DVDD33_3) U1.F5(DVDD33_4) U1.H19(DVDD33_1) U1.J19(DVDD33_2) ; also on sheet 5 6 7 8 17 18 19
3V3_MOS_FLASH: C29.1 C36.1(A) C63.1(A) C93.1(A) C105.1(A) C142.1(A) C143.1(A) C275.1(A) C323.1(A) C324.1(A) D1.1(K) R12.1(A) R29.1(A) R58.1(A) R80.1(A) R81.2(B) R109.2(B) R111.1(A) R176.1(A) R177.1(A) R188.1(A) R189.1(A) R202.1(A) R203.1(A) R212.1(A) R215.1(A) U19.1(NC1/VDD3) U19.12(VDD1) U19.24(NC15/VDD4) U19.34(NC21/VDDQ1) U19.37(VDD2) U22.AA3(VDD_4) U22.AA5(VDD_5) U22.K6(VDD_1) U22.M6(VDDF_1) U22.N5(VDDF_2) U22.T10(VDDF_3) U22.U9(VDDF_4) U22.W4(VDD_2) U22.Y4(VDD_3)
3V3_SD: C263.1(A) C391.1(A) J21.4(P4) Q15.3(D) R92.2(B) R210.1(A)
3V3_WIFI: C15.1(A) C61.1(A) J9.5(DVDD33) LB4.1 U2.5(VDD3.3) U7.8(VDD3.3)
5V0_MOS: C49.1(A) C377.1(A) LB2.2 LB3.2 R113.2(B) R220.2(B) U16.1(IN) U26.1(IN) ; also on sheet 5 16 19
AVDD11_PLL012: C12.1(A) C185.1(A) LB21.2(B) U1.P17(AVDD11_PLL)
AVDD33_PLL01: C14.1(A) C186.1(A) LB22.2(B) U1.R19(AVDD33_PLL)
GND: C1.2(B) C12.2(B) C13.2(B) C14.2(B) C15.2(B) C19.2(B) C21.2(B) C22.2(B) C29.2 C31.2(B) C34.2(B) C36.2(B) C47.2(B) C48.2(B) C49.2(B) C50.2(B) C52.2(B) C56.2(B) C61.2(B) C63.2(B) C64.2 C66.2 C75.2(B) C86.2(B) C87.2(B) C93.2(B) C105.2(B) C106.2(B) C107.2(B) C108.2(B) C115.2(B) C120.2(B) C121.2(B) C123.2(B) C124.2(B) C127.2(B) C132.2(B) C135.2(B) C138.2(B) C142.2(B) C143.2(B) C177.2(B) C185.2(B) C186.2(B) C189.2(B) C193.2(B) C197.2(B) C198.2(B) C199.2(B) C203.2(B) C206.2(B) C211.2(B) C212.2(B) C213.2(B) C214.2(B) C215.2(B) C216.2(B) C218.2(B) C219.2(B) C220.2(B) C227.2(B) C228.2(B) C229.2(B) C230.2(B) C231.2(B) C232.2(B) C233.2(B) C234.2(B) C235.2(B) C236.2(B) C237.2(B) C238.2(B) C239.2(B) C240.2(B) C242.2(B) C243.2(B) C245.2(B) C255.1(A) C257.2(B) C258.2(B) C263.2(B) C265.2(B) C271.2(B) C275.2(B) C282.2(B) C283.2(B) C289.2(B) C308.2(B) C310.2(B) C313.2(B) C314.2(B) C315.2(B) C319.2(B) C323.2(B) C324.2(B) C328.2(B) C330.2(B) C377.2(B) C391.2(B) D2.2(GND) D3.2(GND) D4.2(B) D5.2(B) D7.2(B) D10.2(B) D15.2(B) J2.4(GND) J2.5(M1) J2.6(M2) J6.2 J6.3 J9.2(GND1) J9.7(GND5) J9.9(GND3) J9.10(GND2) J9.12(GND4) J11.2 J11.3 J12.4(GND) J12.5(M1) J12.6(M2) J21.3(P3) J21.6(P6) J21.11(P11) J28.4(GND1) J28.7(GND2) J28.10(S1) J28.11(S2) LED1.2(C) LED2.2(C) Q1.2(E) Q2.2(E) Q5.2(E) R39.2(B) R46.1(A) R55.2(B) R57.2(B) R71.1(A) R75.2(B) R84.2(B) R89.2(B) R106.1(A) R107.2(B) R111.2(B) R115.1(A) R149.2(B) R210.2(B) RN5.2 RN5.7 RN7.2 RN7.7 RN10.2 RN10.7 RN14.2 RN14.7 S2.2 S2.3 S2.4 S3.2 S3.3 S3.4 U1.A1(VSS_47) U1.A2(VSS_48) U1.AA2(VSS_100) U1.AA3(VSS_99) U1.AA8(VSS_98) U1.AA13(VSS_97) U1.AA14(VSS_92) U1.AA15(VSS_91) U1.AA17(VSS_90) U1.AA18(VSS_89) U1.AA20(VSS_96) U1.AB1(VSS_95) U1.AB4(VSS_94) U1.AB6(VSS_93) U1.AB10(VSS_54) U1.AB12(VSS_27) U1.AC1(VSS_56) U1.AC3(VSS_55) U1.AC5(VSS_59) U1.AC9(VSS_65) U1.AC11(VSS_74) U1.AC23(VSS_88) U1.B20(VSS_50) U1.C3(VSS_66) U1.C13(VSS_104) U1.C20(VSS_49) U1.D9(VSS_103) U1.D13(VSS_69) U1.D19(VSS_67) U1.E4(VSS_68) U1.F4(VSS_70) U1.G3(VSS_105) U1.G4(VSS_71) U1.G12(VSS_101) U1.G13(VSS_102) U1.G16(VSS_51) U1.H3(VSS_72) U1.H10(VSS_16) U1.H11(VSS_31) U1.H12(VSS_32) U1.H13(VSS_21) U1.H14(VSS_23) U1.H15(VSS_35) U1.H20(VSS_41) U1.J2(VSS_42) U1.J10(VSS_17) U1.J11(VSS_36) U1.J12(VSS_37) U1.J15(VSS_40) U1.J20(VSS_43) U1.K1(VSS_44) U1.K3(VSS_45) U1.K5(VSS_46) U1.K10(VSS_20) U1.K11(VSS_24) U1.K12(VSS_25) U1.K15(VSS_34) U1.K16(VSS_33) U1.L3(VSS_29) U1.L4(VSS_30) U1.L11(VSS_18) U1.L12(VSS_19) U1.L15(VSS_22) U1.M6(VSS_13) U1.M8(VSS_80) U1.M11(VSS_14) U1.M12(VSS_15) U1.M15(VSS_52) U1.M20(VSS_86) U1.N2(VSS_85) U1.N3(VSS_82) U1.N5(VSS_81) U1.N15(VSS_75) U1.N16(VSS_26) U1.N17(VSS_73) U1.P1(VSS_87) U1.P5(VSS_63) U1.P16(VSS_38) U1.P19(AVSS_PLL) U1.P20(VSS_64) U1.R2(VSS_62) U1.R4(VSS_61) U1.R6(VSS_60) U1.R20(VSS_58) U1.T1(VSS_57) U1.T11(VSS_39) U1.U2(VSS_12) U1.U5(VSS_11) U1.U20(VSS_10) U1.V4(VSS_3) U1.V10(VSS_7) U1.V21(VSS_6) U1.W3(VSS_9) U1.W8(VSS_5) U1.W11(VSS_1) U1.W13(VSS_8) U1.W15(VSS_2) U1.W19(VSS_4) U1.W21(VSS_79) U1.Y1(VSS_78) U1.Y3(VSS_77) U1.Y7(VSS_28) U1.Y9(VSS_76) U1.Y18(VSS_84) U1.Y20(VSS_83) U1.Y23(VSS_53) U2.1(GND) U2.6(RFGND) U3.A9(VSS1) U3.B1(VSSQ1) U3.B3(VSS2) U3.B9(VSSQ2) U3.D1(VSSQ3) U3.D8(VSSQ4) U3.E1(VSS3) U3.E2(VSSQ5) U3.E8(VSSQ6) U3.F9(VSSQ7) U3.G1(VSSQ8) U3.G8(VSS4) U3.G9(VSSQ9) U3.J2(VSS5) U3.J8(VSS6) U3.M1(VSS7) U3.M9(VSS8) U3.P1(VSS9) U3.P9(VSS10) U3.T1(VSS11) U3.T9(VSS12) U6.A9(VSS1) U6.B1(VSSQ1) U6.B3(VSS2) U6.B9(VSSQ2) U6.D1(VSSQ3) U6.D8(VSSQ4) U6.E1(VSS3) U6.E2(VSSQ5) U6.E8(VSSQ6) U6.F9(VSSQ7) U6.G1(VSSQ8) U6.G8(VSS4) U6.G9(VSSQ9) U6.J2(VSS5) U6.J8(VSS6) U6.M1(VSS7) U6.M9(VSS8) U6.P1(VSS9) U6.P9(VSS10) U6.T1(VSS11) U6.T9(VSS12) U7.1(RFGND1) U7.5(GND) U16.2(GND) U19.2(NC2/VSS3) U19.13(VSS1) U19.23(NC14/VSS4) U19.25(NC16/VSS5) U19.36(VSS2) U19.48(NC29/VSS6) U22.AA4(VSS_8) U22.AA6(VSS_9) U22.K4(VSS_1) U22.M7(VSS_2) U22.P5(VSS_3) U22.R10(VSS_4) U22.U8(VSS_5) U22.Y2(VSS_6) U22.Y5(VSS_7) U26.2(GND) ; also on sheet 3 4 5 6 7 8 16 17 18 19
DDR_ADDR0: RN2.1 RN11.8 ; also on sheet 8
DDR_ADDR0_A: RN2.8 U3.N3(A0)
DDR_ADDR0_B: RN11.1 U6.N3(A0)
DDR_ADDR1: RN4.3 RN13.6 ; also on sheet 8
DDR_ADDR1_A: RN4.6 U3.P7(A1)
DDR_ADDR1_B: RN13.3 U6.P7(A1)
DDR_ADDR2: RN1.4 RN9.5 ; also on sheet 8
DDR_ADDR2_A: RN1.5 U3.P3(A2)
DDR_ADDR2_B: RN9.4 U6.P3(A2)
DDR_ADDR3: RN2.2 RN11.7 ; also on sheet 8
DDR_ADDR3_A: RN2.7 U3.N2(A3)
DDR_ADDR3_B: RN11.2 U6.N2(A3)
DDR_ADDR4: RN4.4 RN13.5 ; also on sheet 8
DDR_ADDR4_A: RN4.5 U3.P8(A4)
DDR_ADDR4_B: RN13.4 U6.P8(A4)
DDR_ADDR5: RN2.3 RN11.6 ; also on sheet 8
DDR_ADDR5_A: RN2.6 U3.P2(A5)
DDR_ADDR5_B: RN11.3 U6.P2(A5)
DDR_ADDR6: RN4.2 RN13.7 ; also on sheet 8
DDR_ADDR6_A: RN4.7 U3.R8(A6)
DDR_ADDR6_B: RN13.2 U6.R8(A6)
DDR_ADDR7: RN2.4 RN11.5 ; also on sheet 8
DDR_ADDR7_A: RN2.5 U3.R2(A7)
DDR_ADDR7_B: RN11.4 U6.R2(A7)
DDR_ADDR8: RN4.1 RN13.8 ; also on sheet 8
DDR_ADDR8_A: RN4.8 U3.T8(A8)
DDR_ADDR8_B: RN13.1 U6.T8(A8)
DDR_ADDR9: RN1.2 RN9.7 ; also on sheet 8
DDR_ADDR9_A: RN1.7 U3.R3(A9)
DDR_ADDR9_B: RN9.2 U6.R3(A9)
DDR_ADDR10: RN6.3 RN8.6 ; also on sheet 8
DDR_ADDR10_A: RN6.6 U3.L7(A10/AP)
DDR_ADDR10_B: RN8.3 U6.L7(A10/AP)
DDR_ADDR11: RN5.3 RN10.6 ; also on sheet 8
DDR_ADDR11_A: RN5.6 U3.R7(A11)
DDR_ADDR11_B: RN10.3 U6.R7(A11)
DDR_ADDR12: RN6.2 RN8.7 ; also on sheet 8
DDR_ADDR12_A: RN6.7 U3.N7(A12/BC~)
DDR_ADDR12_B: RN8.2 U6.N7(A12/BC~)
DDR_ADDR13: RN1.3 RN9.6 ; also on sheet 8
DDR_ADDR13_A: RN1.6 U3.T3(A13)
DDR_ADDR13_B: RN9.3 U6.T3(A13)
DDR_ADDR14: RN5.4 RN10.5 ; also on sheet 8
DDR_ADDR14_A: RN5.5 U3.T7(A14)
DDR_ADDR14_B: RN10.4 U6.T7(A14)
DDR_ADDR15: RN5.1 RN10.8 ; also on sheet 8
DDR_ADDR15_A: RN5.8 U3.M7(NC5)
DDR_ADDR15_B: RN10.1 U6.M7(NC5)
DDR_BA0: RN7.4 RN14.5 ; also on sheet 8
DDR_BA0_A: RN7.5 U3.M2(BA0)
DDR_BA0_B: RN14.4 U6.M2(BA0)
DDR_BA1: RN6.1 RN8.8 ; also on sheet 8
DDR_BA1_A: RN6.8 U3.N8(BA1)
DDR_BA1_B: RN8.1 U6.N8(BA1)
DDR_BA2: RN3.2 RN12.7 ; also on sheet 8
DDR_BA2_A: RN3.7 U3.M3(BA2)
DDR_BA2_B: RN12.2 U6.M3(BA2)
DDR_CASN: RN3.4 RN12.5 ; also on sheet 8
DDR_CASN_A: RN3.5 U3.K3(~{CAS})
DDR_CASN_B: RN12.4 U6.K3(~{CAS})
DDR_CKE: RN6.4 RN8.5 ; also on sheet 8
DDR_CKE_A: RN6.5 U3.K9(CKE)
DDR_CKE_B: RN8.4 U6.K9(CKE)
DDR_CLK0N: R11.1(A) U3.K7(~{CK}) ; also on sheet 8
DDR_CLK0P: R15.2(B) U3.J7(CK) ; also on sheet 8
DDR_CLK1N: R16.1(A) U6.K7(~{CK}) ; also on sheet 8
DDR_CLK1P: R17.2(B) U6.J7(CK) ; also on sheet 8
DDR_CSN: RN3.1 RN12.8 ; also on sheet 8
DDR_CSN_A: RN3.8 U3.L2(~{CS})
DDR_CSN_B: RN12.1 U6.L2(~{CS})
DDR_DM0: U3.E7(LDM) ; also on sheet 8
DDR_DM1: U3.D3(UDM) ; also on sheet 8
DDR_DM2: U6.E7(LDM) ; also on sheet 8
DDR_DM3: U6.D3(UDM) ; also on sheet 8
DDR_DQ0: U3.E3(DQ0) ; also on sheet 8
DDR_DQ1: U3.F7(DQ1) ; also on sheet 8
DDR_DQ2: U3.F2(DQ2) ; also on sheet 8
DDR_DQ3: U3.F8(DQ3) ; also on sheet 8
DDR_DQ4: U3.H3(DQ4) ; also on sheet 8
DDR_DQ5: U3.H8(DQ5) ; also on sheet 8
DDR_DQ6: U3.G2(DQ6) ; also on sheet 8
DDR_DQ7: U3.H7(DQ7) ; also on sheet 8
DDR_DQ8: U3.D7(DQ8) ; also on sheet 8
DDR_DQ9: U3.C3(DQ9) ; also on sheet 8
DDR_DQ10: U3.C8(DQ10) ; also on sheet 8
DDR_DQ11: U3.C2(DQ11) ; also on sheet 8
DDR_DQ12: U3.A7(DQ12) ; also on sheet 8
DDR_DQ13: U3.A2(DQ13) ; also on sheet 8
DDR_DQ14: U3.B8(DQ14) ; also on sheet 8
DDR_DQ15: U3.A3(DQ15) ; also on sheet 8
DDR_DQ16: U6.E3(DQ0) ; also on sheet 8
DDR_DQ17: U6.F7(DQ1) ; also on sheet 8
DDR_DQ18: U6.F2(DQ2) ; also on sheet 8
DDR_DQ19: U6.F8(DQ3) ; also on sheet 8
DDR_DQ20: U6.H3(DQ4) ; also on sheet 8
DDR_DQ21: U6.H8(DQ5) ; also on sheet 8
DDR_DQ22: U6.G2(DQ6) ; also on sheet 8
DDR_DQ23: U6.H7(DQ7) ; also on sheet 8
DDR_DQ24: U6.D7(DQ8) ; also on sheet 8
DDR_DQ25: U6.C3(DQ9) ; also on sheet 8
DDR_DQ26: U6.C8(DQ10) ; also on sheet 8
DDR_DQ27: U6.C2(DQ11) ; also on sheet 8
DDR_DQ28: U6.A7(DQ12) ; also on sheet 8
DDR_DQ29: U6.A2(DQ13) ; also on sheet 8
DDR_DQ30: U6.B8(DQ14) ; also on sheet 8
DDR_DQ31: U6.A3(DQ15) ; also on sheet 8
DDR_DQS0N: U3.G3(~{LDQS}) ; also on sheet 8
DDR_DQS0P: U3.F3(LDQS) ; also on sheet 8
DDR_DQS1N: U3.B7(~{UDQS}) ; also on sheet 8
DDR_DQS1P: U3.C7(UDQS) ; also on sheet 8
DDR_DQS2N: U6.G3(~{LDQS}) ; also on sheet 8
DDR_DQS2P: U6.F3(LDQS) ; also on sheet 8
DDR_DQS3N: U6.B7(~{UDQS}) ; also on sheet 8
DDR_DQS3P: U6.C7(UDQS) ; also on sheet 8
DDR_ODT: RN7.3 RN14.6 ; also on sheet 8
DDR_ODT_A: RN7.6 U3.K1(ODT)
DDR_ODT_B: RN14.3 U6.K1(ODT)
DDR_RASN: RN7.1 RN14.8 ; also on sheet 8
DDR_RASN_A: RN7.8 U3.J3(~{RAS})
DDR_RASN_B: RN14.1 U6.J3(~{RAS})
DDR_RESETN: RN1.1 RN9.8 ; also on sheet 8
DDR_RESETN_A: C313.1(A) R47.2(B) RN1.8 U3.T2(~{RESET})
DDR_RESETN_B: C314.1(A) R49.2(B) RN9.1 U6.T2(~{RESET})
DDR_VREF_CA_A: C207.2(B) C289.1(A) R51.2(B) R55.1(A) U3.M8(VREFCA)
DDR_VREF_CA_B: C222.2(B) C310.1(A) R103.2(B) R107.1(A) U6.M8(VREFCA)
DDR_VREF_DQ_A: C208.2(B) C271.1(A) R54.2(B) R75.1(A) U3.H1(VREFDQ)
DDR_VREF_DQ_B: C223.2(B) C308.1(A) R78.2(B) R84.1(A) U6.H1(VREFDQ)
DDR_WEN: RN3.3 RN12.6 ; also on sheet 8
DDR_WEN_A: RN3.6 U3.L3(~{WE})
DDR_WEN_B: RN12.3 U6.L3(~{WE})
IR_IN: D2.1(OUT) D3.1(OUT) R140.1(A) ; also on sheet 6
LED_GREEN: R3.2(B) R22.1(A) R57.1(A) ; also on sheet 6
LED_RED: R31.1(A) R39.1(A) R69.2(B) ; also on sheet 6
NF_ALE_EMMC_PWREN: U19.17(ALE) ; also on sheet 6
NF_CLE: U19.16(CLE) ; also on sheet 6
NF_CSN0_EMMC_CMD: R212.2(B) U19.9(~{CE}) U22.W5(CMD) ; also on sheet 6
NF_DQ0_EMMC_D0: R189.2(B) U19.29(I/O0) U22.H3(DAT0) ; also on sheet 6
NF_DQ1_EMMC_D1: R12.2(B) U19.30(I/O1) U22.H4(DAT1) ; also on sheet 6
NF_DQ2_EMMC_D2: R29.2(B) U19.31(I/O2) U22.H5(DAT2) ; also on sheet 6
NF_DQ3_EMMC_D3: R58.2(B) U19.32(I/O3) U22.J2(DAT3) ; also on sheet 6
NF_DQ4_EMMC_D4: R176.2(B) U19.41(I/O4) U22.J3(DAT4) ; also on sheet 6
NF_DQ5_EMMC_D5: R177.2(B) U19.42(I/O5) U22.J4(DAT5) ; also on sheet 6
NF_DQ6_EMMC_D6: R188.2(B) U19.43(I/O6) U22.J5(DAT6) ; also on sheet 6
NF_DQ7_EMMC_D7_BOOT_SEL0: R202.2(B) U19.44(I/O7) U22.J6(DAT7) ; also on sheet 6
NF_RDY0_EMMC_RST: C115.1(A) R203.2(B) U19.7(R/B~) U22.U5(RSTN) ; also on sheet 6
NF_REN_EMMC_CLK: U19.8(~{RE}) U22.W6(CLK) ; also on sheet 6
NF_WEN_EMMC_DET: U19.18(~{WE}) ; also on sheet 6
NF_WP: R89.1(A) R215.2(B) U19.19(~{WP})
POWER_STB: C21.1(A) C22.1(A) R41.2(B) S2.1 S3.1 ; also on sheet 6
RF0: C86.1(A) L1.2(B) U7.3(RF0)
RF1: C56.1(A) L7.2(B) U2.7(RF) U7.2(RF1)
RFF0: C48.1(A) J11.1 L1.1(A)
RFF1: C50.1(A) J6.1 L7.1(A)
SDIO0_CARD_DETECT: J21.10(P10) R155.2(B) ; also on sheet 6
SDIO0_CCLK_OUT: J21.5(P5) ; also on sheet 6
SDIO0_CCMD: J21.2(P2) R153.2(B) ; also on sheet 6
SDIO0_CDATA0: J21.7(P7) R152.2(B) ; also on sheet 6
SDIO0_CDATA1: J21.8(P8) R151.2(B) ; also on sheet 6
SDIO0_CDATA2: J21.9(P9) R156.2(B) ; also on sheet 6
SDIO0_CDATA3: J21.1(P1) R154.2(B) ; also on sheet 6
SDIO0_CWPR: J21.12(P12) R24.2(B) ; also on sheet 6
SDIO0_PWREN: R76.1(A) R149.1(A) ; also on sheet 6
SDIO_3318: R24.1(A) R151.1(A) R152.1(A) R153.1(A) R154.1(A) R156.1(A) ; also on sheet 6
USB0_DM: C87.1(A) D5.1(A) J12.2(D-) ; also on sheet 7
USB0_DP: C75.1(A) D4.1(A) J12.3(D+) ; also on sheet 7
USB1_DM: J9.4(D-) U2.4(DM) U7.7(DM) ; also on sheet 7
USB1_DP: J9.3(D+) U2.2(DP) U7.6(DP) ; also on sheet 7
USB2_DM: D10.1(A) J2.2(D-) ; also on sheet 6
USB2_DP: D15.1(A) J2.3(D+) ; also on sheet 6
USB3_DM: J28.2(D-) ; also on sheet 6
USB3_DP: J28.3(D+) ; also on sheet 6
USB3_RXN: J28.5(RX-) ; also on sheet 6
USB3_RXP: J28.6(RX+) ; also on sheet 6
USB3_TXN: C62.2(B) ; also on sheet 6
USB3_TXP: C70.2(B) ; also on sheet 6
USB3_VBUS: C52.1(A) C66.1 J2.1(VBUS) J28.1(VBUS) LB3.1 U16.5(OUT)
N03171: D7.1(A) LED1.3(A2) LED2.3(A2) Q1.3(C) R2.2(B)
N03193: LED1.1(A1) LED2.1(A1) Q2.3(C) R34.2(B)
N03237: C47.1(A) C177.1(A) D2.3(VCC) D3.3(VCC) R178.1(A)
N03347: Q5.3(C) R267.2(B)
N03351: Q5.1(B) R76.2(B)
N03375: C73.2(B) Q15.1(G) R77.2(B) R267.1(A)
N03389: Q1.1(B) R22.2(B)
N03437: Q2.1(B) R31.2(B)
N04493: C64.1 C265.1(A) J12.1(VBUS) LB2.1 U26.5(OUT)
N04567: R115.2(B) U16.4(ILIM)
N04573: R113.1(A) U16.3(EN)
N04603: R106.2(B) U26.4(ILIM)
N04609: R220.1(A) U26.3(EN)
N06162: R81.1(A) U19.39(NC24)
N07402: C330.1(A) R16.2(B) R17.1(A)
N08088: R71.2(B) U6.L8(ZQ)
N09537: C328.1(A) R11.2(B) R15.1(A)
N09803: R46.2(B) U3.L8(ZQ)
N11810: C255.2(B) U1.T19(DVDD11_LDO_DECAP)
N4772245: C123.1(A) C124.1(A) U22.K2(VDDI)
N5193332: C62.1(A) J28.8(TX-)
N5193336: C70.1(A) J28.9(TX+)
N16921380: R80.2(B) U19.38(NC23/VDDQ2)

Not connected (* = marked no-connect by the designer): J9 1(NC1)* 6(NC2)* 8(RF0)* 11(RF1)*; U2 3(VDD+)*; U3 J1(NC1)* J9(NC2)* L1(NC3)* L9(NC4)*; U6 J1(NC1)* J9(NC2)* L1(NC3)* L9(NC4)*; U7 4(XI)* 9(SUSPEND)* 10(WO_WLAN)*; U19 3(NC3)* 4(NC4)* 5(NC5)* 6(NC6)* 10(NC7)* 11(NC8)* 14(NC9)* 15(NC10)* 20(NC11)* 21(NC12)* 22(NC13)* 26(NC17) 27(NC18) 28(NC19) 33(NC20) 35(NC22)* 40(NC25) 45(NC26) 46(NC27) 47(NC28); U22 A4(NC_1)* A6(NC_2)* A9(NC_3)* A11(NC_4)* AA1(NC_122)* AA2(NC_123)* AA7(NC_124)* AA8(NC_125)* AA9(NC_126)* AA10(NC_127)* AA11(NC_128)* AA12(NC_129)* AA13(NC_130)* AA14(NC_131)* AE1(NC_132)* AE14(NC_133)* AG2(NC_134)* AG13(NC_135)* AH4(NC_136)* AH6(NC_137)* AH9(NC_138)* AH11(NC_95)* B2(NC_5)* B13(NC_6)* D1(NC_7)* D14(NC_8)* H1(NC_9)* H2(NC_10)* H6(NC_11)* H7(NC_12)* H8(NC_13)* H9(NC_14)* H10(NC_15)* H11(NC_16)* H12(NC_17)* H13(NC_18)* H14(NC_19)* J1(NC_20)* J7(NC_21)* J8(NC_22)* J9(NC_23)* J10(NC_24)* J11(NC_25)* J12(NC_26)* J13(NC_27)* J14(NC_28)* K1(NC_29)* K3(NC_30)* K5(NC_31)* K7(NC_32)* K8(NC_33)* K9(NC_34)* K10(NC_35)* K11(NC_36)* K12(NC_37)* K13(NC_38)* K14(NC_39)* L1(NC_40)* L2(NC_41)* L3(NC_42)* L4(A1)* L12(NC_43)* L13(NC_44)* L14(NC_45)* M1(NC_46)* M2(NC_47)* M3(NC_48)* M5(NC_49)* M8(NC_50)* M9(NC_51)* M10(NC_52)* M12(NC_53)* M13(NC_54)* M14(NC_55)* N1(NC_56)* N2(NC_57)* N3(NC_58)* N10(NC_59)* N12(NC_60)* N13(NC_61)* N14(NC_62)* P1(NC_63)* P2(NC_64)* P3(NC_65)* P10(NC_66)* P12(NC_67)* P13(NC_68)* P14(NC_69)* R1(NC_70)* R2(NC_71)* R3(NC_72)* R5(NC_73)* R12(NC_74)* R13(NC_75)* R14(NC_76)* T1(NC_77)* T2(NC_78)* T3(NC_79)* T5(NC_80)* T12(NC_81)* T13(NC_82)* T14(NC_83)* U1(NC_84)* U2(NC_85)* U3(NC_86)* U6(NC_87)* U7(NC_88)* U10(NC_89)* U12(NC_90)* U13(NC_91)* U14(NC_92)* V1(NC_93)* V2(NC_94)* V3(NC_96)* V12(NC_97)* V13(NC_98)* V14(NC_99)* W1(NC_100)* W2(NC_101)* W3(NC_102)* W7(NC_103)* W8(NC_104)* W9(NC_105)* W10(NC_106)* W11(NC_107)* W12(NC_108)* W13(NC_109)* W14(NC_110)* Y1(NC_111)* Y3(NC_112)* Y6(NC_113)* Y7(NC_114)* Y8(NC_115)* Y9(NC_116)* Y10(NC_117)* Y11(NC_118)* Y12(NC_119)* Y13(NC_120)* Y14(NC_121)*

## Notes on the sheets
sheet 9
- Unit 4 of Hi3798MV100(POWER)
sheet 10
- Unit 5 of Hi3798MV100(VSS)
sheet 11
- DDRA
- 1%
- 1%
- 1%
- 1%
- 1%
- 1%
- 1%
sheet 12
- DDRB
- 1%
- 1%
- 1%
- 1%
- 1%
- 1%
- 1%
sheet 13
- NAND FLASH/EMMC
- NAND FLASH
- eMMC/fSD
- fSD  10K
- fSD
- 4GB
- NFWP
- 0:Protect
- H6 eMMC5.0
- 1:NOT Protect
- 4GB
- NAND FLASH
- C142=C143=100NF,C36=1UF,R215=4.7K,R81=0,C29=100UF,D1=DIODE,U19=NAND
- others=NC,If use MICRON NAND FLASH,R81=NC
- eMMC
- Pay attention to pin38&pin39,these pins are NC for the MLC NAND of some
- C63=C123=C124=C93=C105=C323=C324=100NF,C275=2.2UF
- R203=R189=R12=R29=R58=R176=R177=R188=R202=47K,R212=10K,R109=0,U22=eMMC,others=NC
- brands(such as Micron),but it should be connected to the VCC of
- others(such as Toshiba and Hynix).
- fSD
- T5 eMMC5.0
- Pls refer to the corresponding datasheet for detail.
- C63=C123=C124=C93=C105=C323=C324=100NF,C275=2.2UF
- R203=R189=R12=R29=R58=R212=10K,R109=0,U22=fSD,others=NC
- R5 eMMC5.0
sheet 14
- USB
- USB0:usb_boot/adb
- ETA6010:Current=1.3A
- For Board Antenna
- ANTF:50ohm Resistance
- For Board Antenna
- ANTF:50ohm Resistance
- ETA6010:Current=1.3A
sheet 15
- SD CARD
- LED
- IR
- GREEN
- R ON+G OFF->STBY
- R OFF+G ON->WORK
- R OFF+G OFF->NO POWER
